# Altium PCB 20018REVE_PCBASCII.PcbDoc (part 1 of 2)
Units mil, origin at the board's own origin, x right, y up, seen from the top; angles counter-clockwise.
Board outline 3400 x 2150 mil, 4 copper layers (Top Layer, Signal Layer 1, Signal Layer 2, Bottom Layer), stack 66.258 mil thick; 182 components, 126 nets, 668 pads, 320 vias.
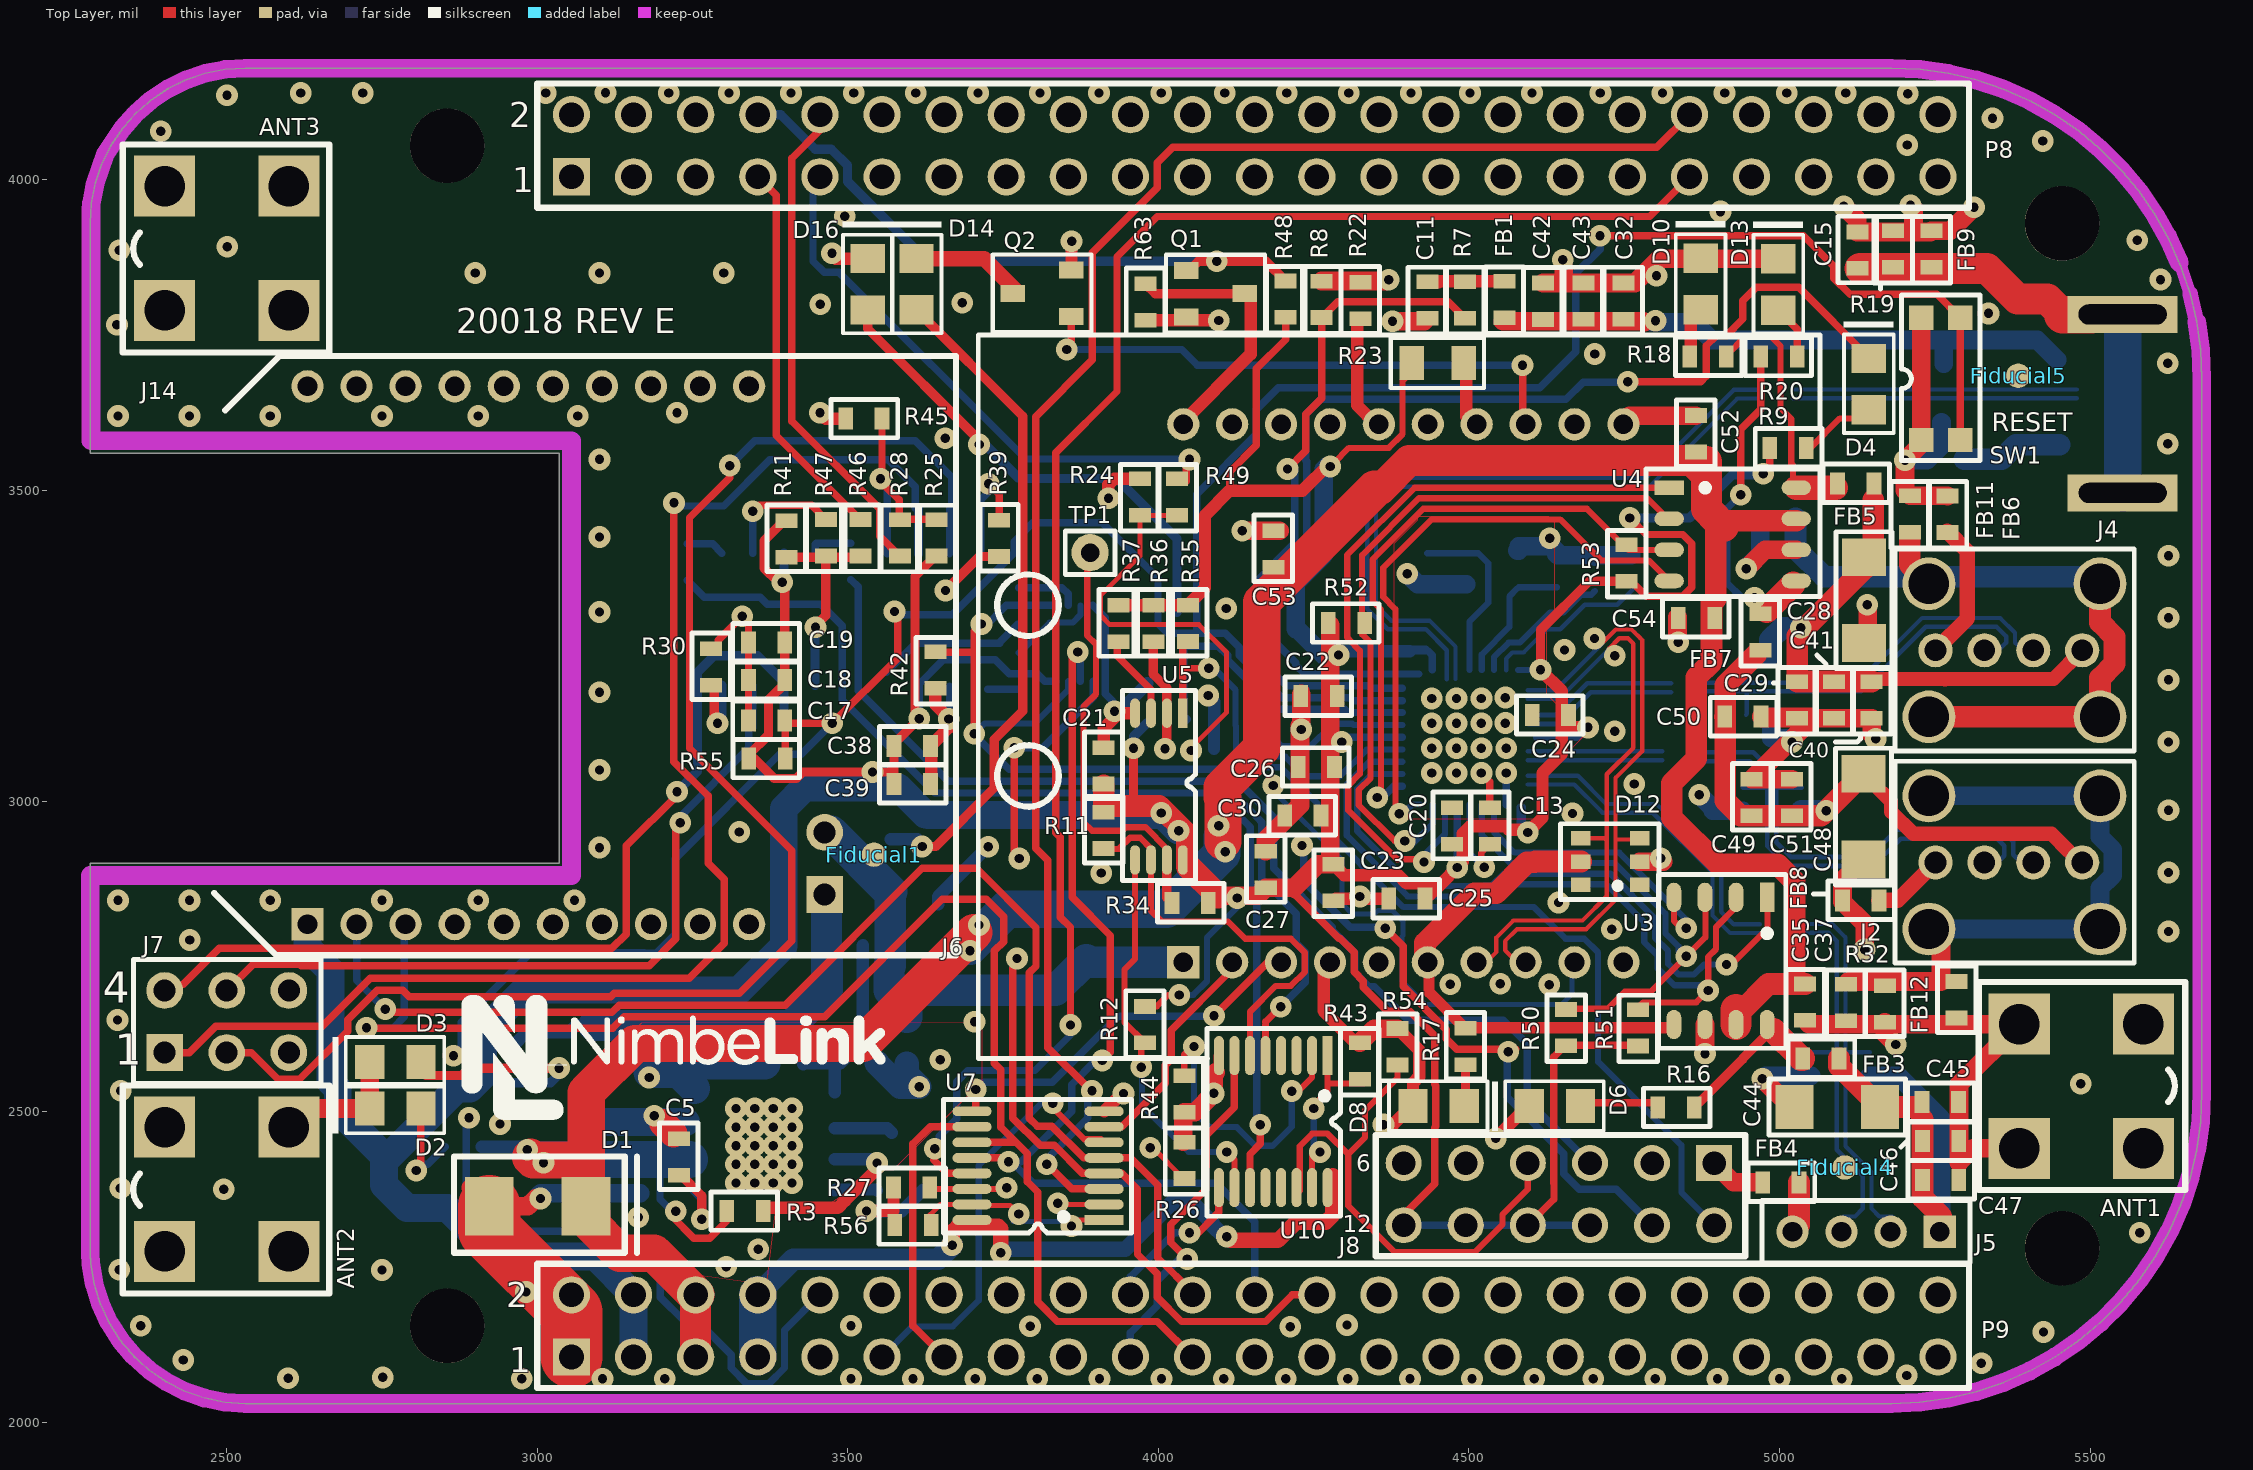
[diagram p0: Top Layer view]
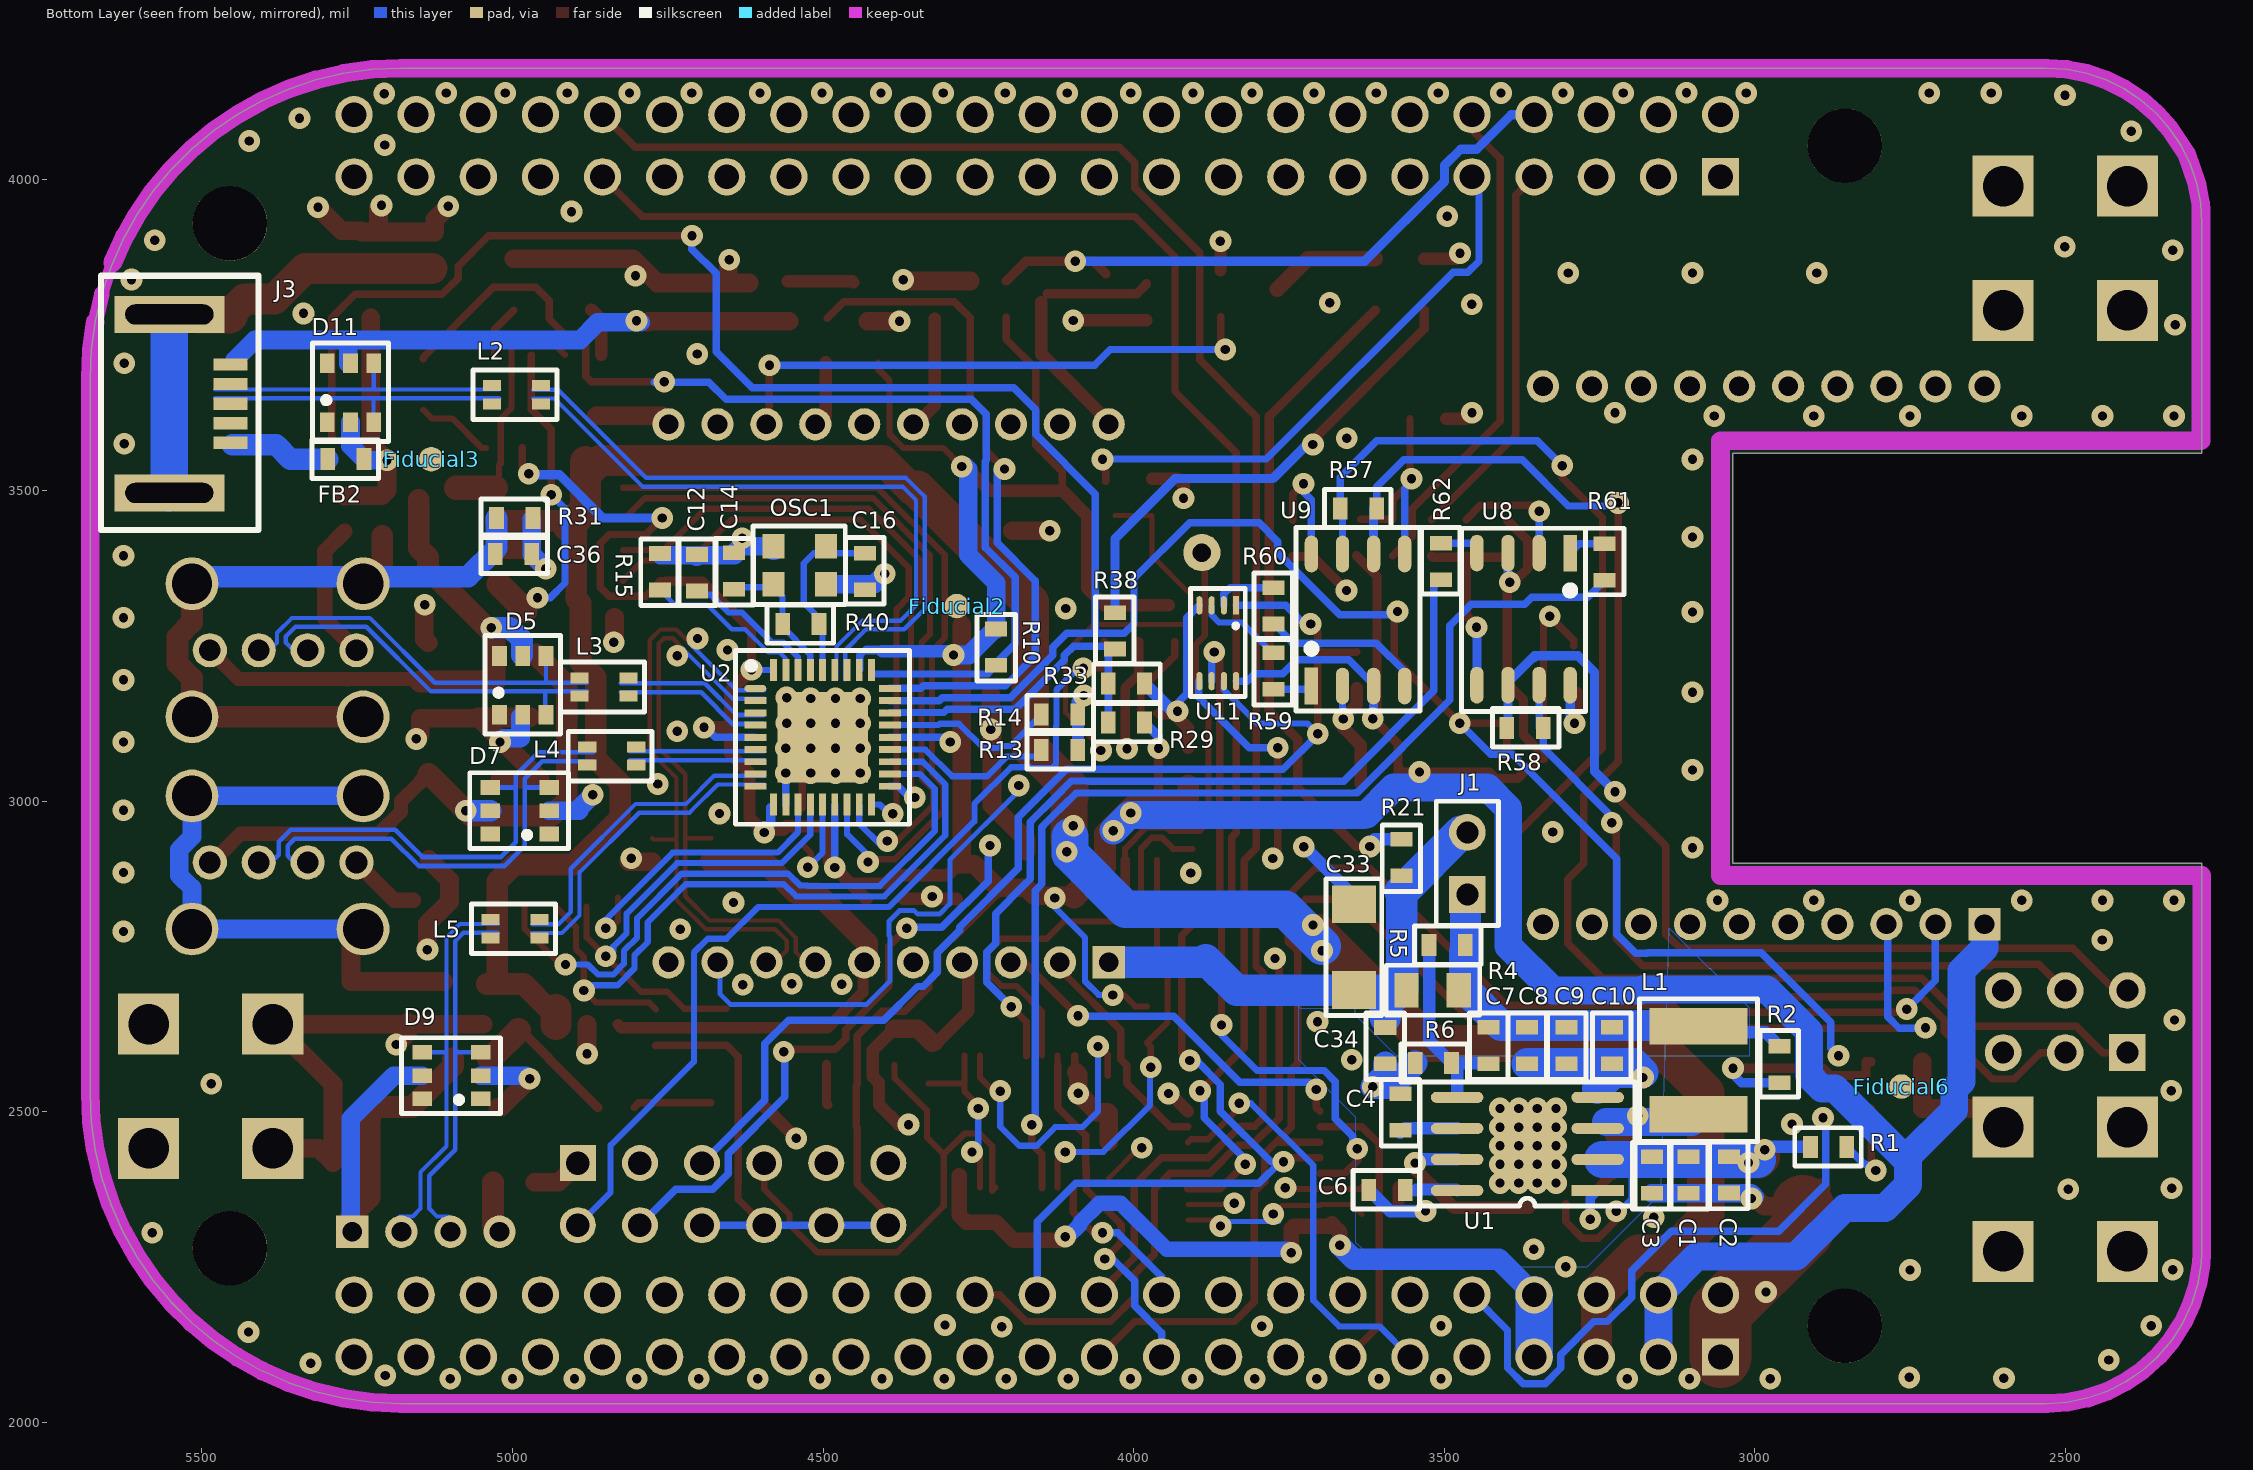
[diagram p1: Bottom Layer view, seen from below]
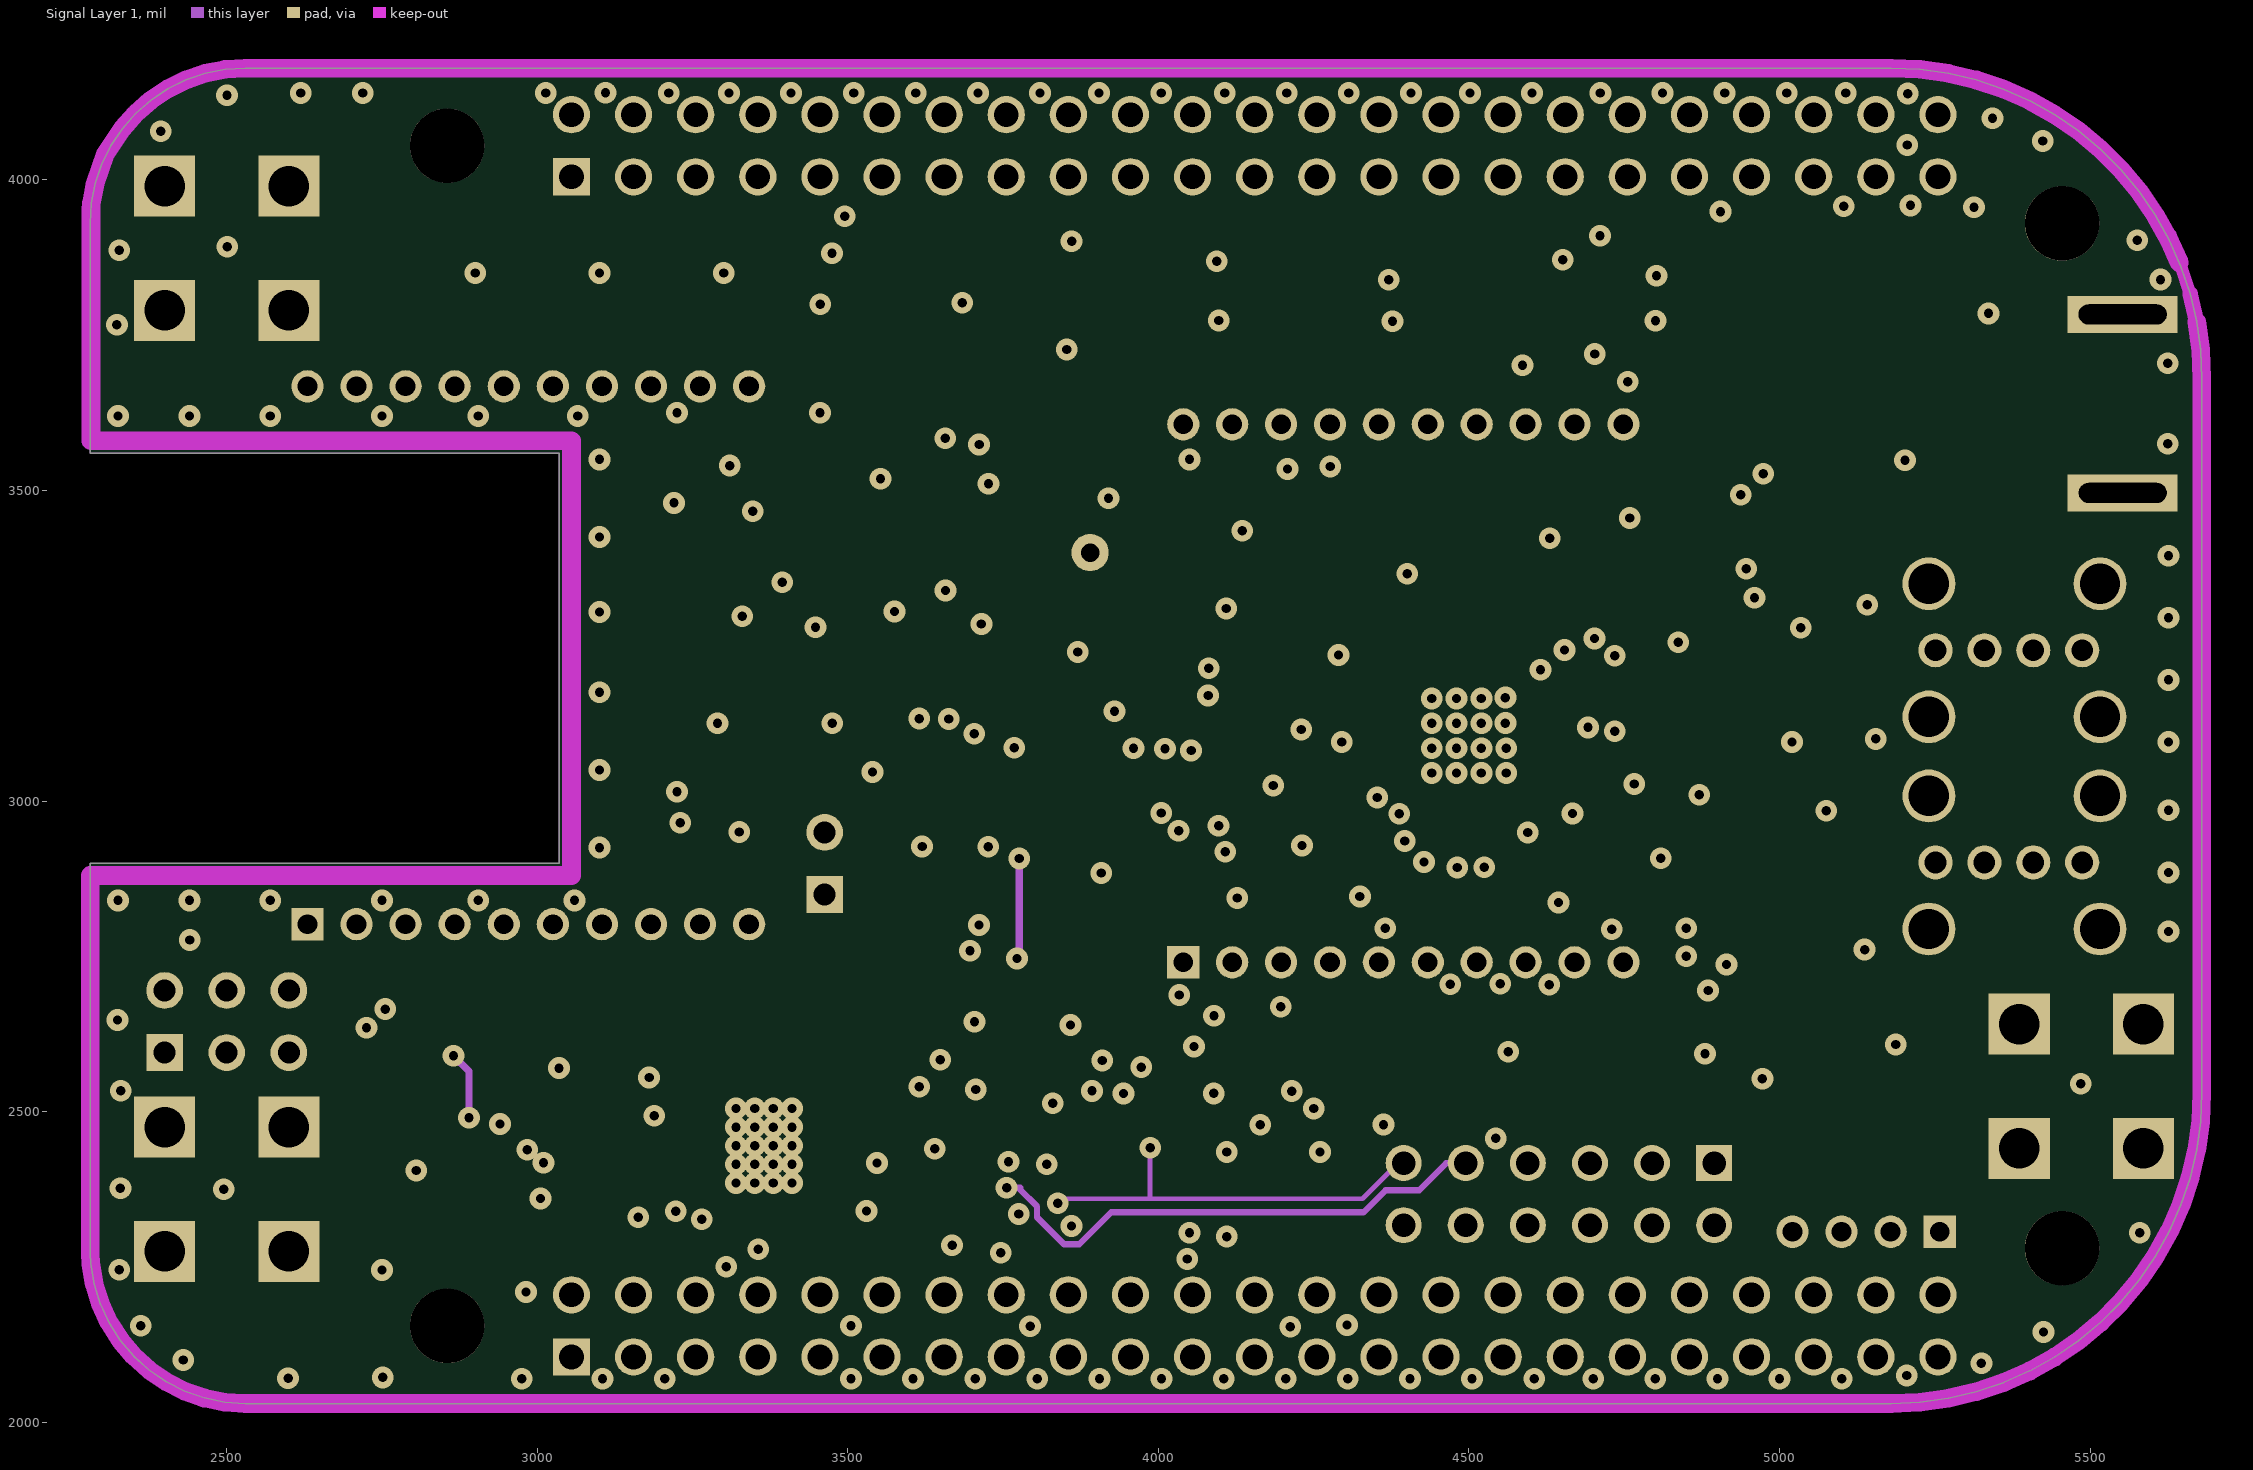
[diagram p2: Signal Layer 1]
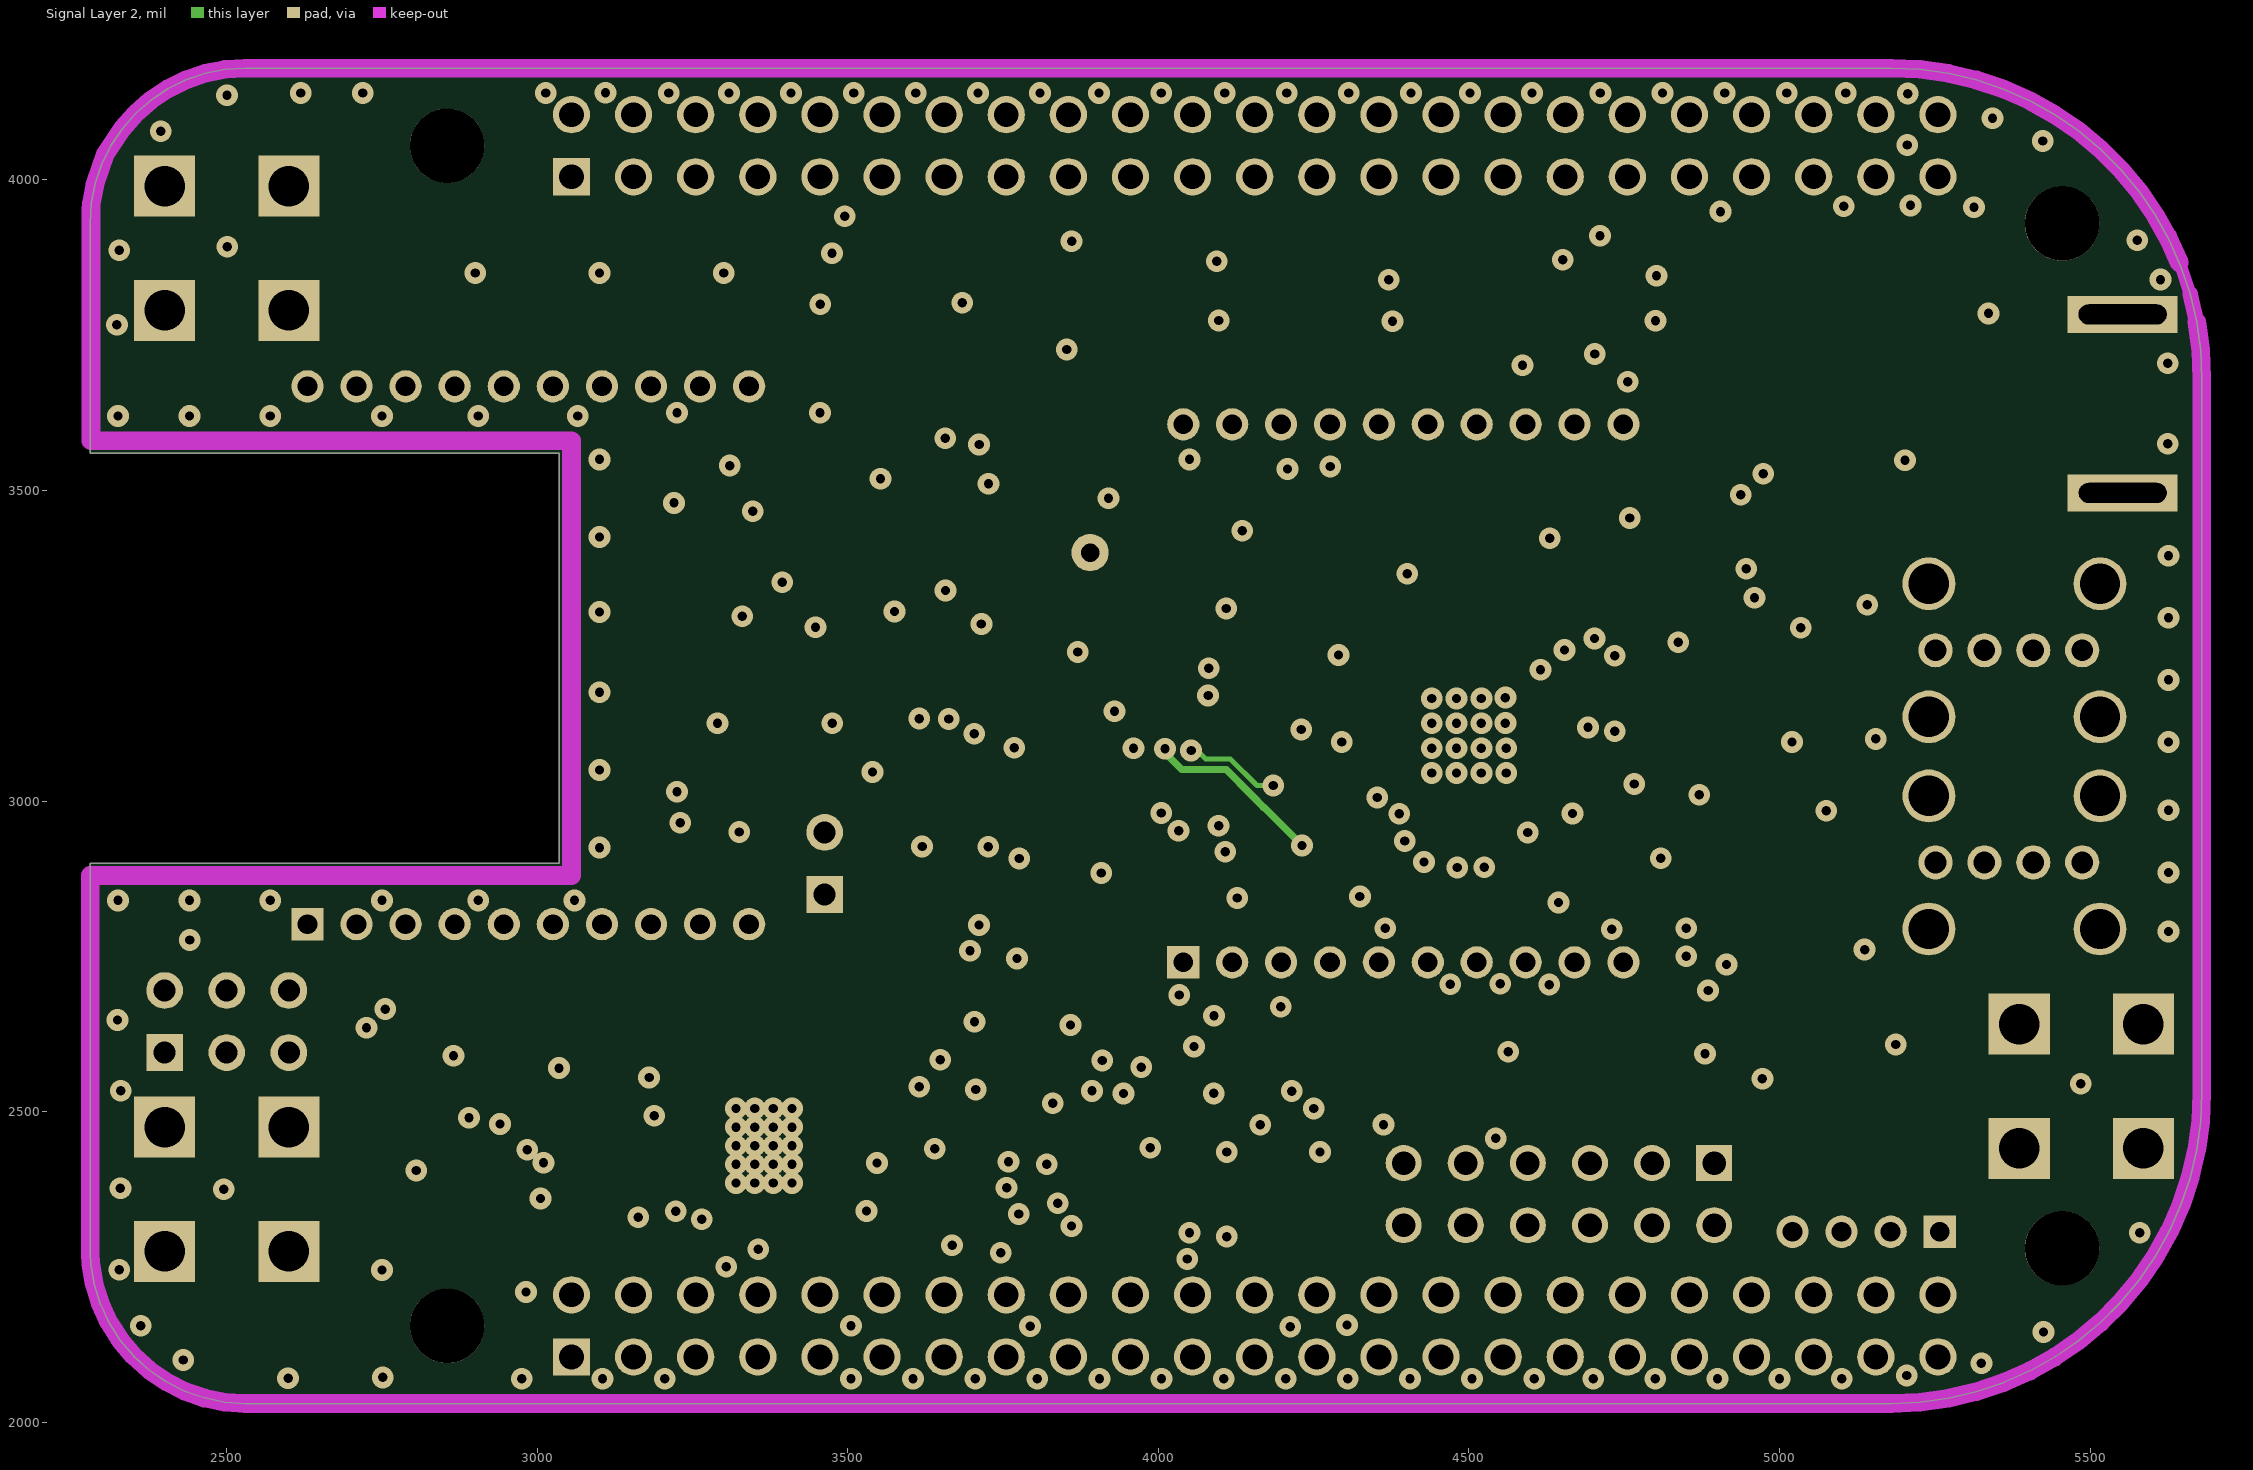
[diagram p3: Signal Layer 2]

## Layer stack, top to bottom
Top Solder: solder mask 0.4, Solder Resist, Dk 3.5
Top Layer: signal copper 1.4
Dielectric 1: prepreg 6.69, FR-4, Dk 4.6
Signal Layer 1: signal copper 1.417
Dielectric 3: core 47.244, Dk 4.6
Signal Layer 2: signal copper 1.417
Dielectric 2: prepreg 6.69, Dk 4.6
Bottom Layer: signal copper 1.4
Bottom Solder: solder mask 0.4, Solder Resist, Dk 3.5

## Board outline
2280,2600 2280,2900 3035,2900 3035,3560 2280,3560 2280,3570 2280,3930 2282.14,3962.63 2288.52,3994.7 2299.03,4025.67 2313.49,4055 2331.66,4082.19 2353.22,4106.78 2377.81,4128.34 2405,4146.51 2434.33,4160.97 2465.3,4171.48 2497.37,4177.86 2530,4180 5180,4180 5226.13,4177.87 5271.87,4171.49 5316.83,4160.91 5360.62,4146.24 5402.87,4127.58 5443.22,4105.11 5481.32,4079.01 5516.85,4049.5 5549.5,4016.85 5579.01,3981.32 5605.11,3943.22 5627.58,3902.87 5646.24,3860.62 5660.91,3816.83 5671.49,3771.87 5677.87,3726.13 5680,3680 5680,2530 5677.87,2483.87 5671.49,2438.12 5660.91,2393.17 5646.24,2349.38 5627.58,2307.13 5605.11,2266.78 5579.01,2228.68 5549.5,2193.15 5516.85,2160.5 5481.32,2130.99 5443.22,2104.89 5402.87,2082.42 5360.62,2063.76 5316.83,2049.09 5271.87,2038.51 5226.13,2032.13 5180,2030 2530,2030 2496.68,2032.23 2463.95,2038.88 2432.4,2049.84 2402.59,2064.9 2375.05,2083.81 2350.28,2106.21 2328.72,2131.72 2310.75,2159.87 2296.7,2190.17 2286.81,2222.07 2281.25,2255 2280.04,2272.11 2280,2320 2280,2483.93

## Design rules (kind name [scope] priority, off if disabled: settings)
AssemblyTestPointUsage [All] p0: scope1count=1 scope1_0_kind=Board scope1_0_value=Board scope2count=1 scope2_0_kind=Board scope2_0_value=Board commentlength=0
AssemblyTestpoint [All] p0: scope1count=1 scope1_0_kind=Board scope1_0_value=Board scope2count=1 scope2_0_kind=Board scope2_0_value=Board commentlength=0
Clearance Clearance_1 [All] p0 off: scope1count=1 scope1_0_kind=Board scope1_0_value=Board scope2count=1 scope2_0_kind=Board scope2_0_value=Board commentlength=69 gap=23.62 // Protel DXP Scope 1 Expression Was: (HasFootprint('Fiducial 1mm'))
Clearance [All] p0: scope1count=1 scope1_0_kind=Board scope1_0_value=Board scope2count=1 scope2_0_kind=Board scope2_0_value=Board commentlength=0 gap=7
Clearance Clearance_1 [(HasFootprint('Fiducial 1mm'))] p1: gap=23.62
Clearance [All] p2: gap=7
ComponentClearance ComponentClearance_1 [All] p0: scope1count=1 scope1_0_kind=Footprint scope1_0_value=BBBC scope2count=1 scope2_0_kind=Board scope2_0_value=Board commentlength=0 gap=0 collisioncheckmode=3
ComponentClearance [All] p0: scope1count=1 scope1_0_kind=Board scope1_0_value=Board scope2count=1 scope2_0_kind=Board scope2_0_value=Board commentlength=0 gap=7 collisioncheckmode=3
ComponentClearance ComponentClearance_1 [HasFootprint('BBBC')] p1: gap=0 collisioncheckmode=3 verticalgap=0 showdistances=FALSE
ComponentClearance [All] p2: gap=7 collisioncheckmode=3 verticalgap=7 showdistances=FALSE
DiffPairsRouting [All] p0: scope1count=1 scope1_0_kind=Board scope1_0_value=Board scope2count=1 scope2_0_kind=Board scope2_0_value=Board commentlength=0
DiffPairsRouting [All] p1: maxlimit=13 minlimit=7 mostfreqgap=7 toplayer_minwidth=7 toplayer_maxwidth=10 toplayer_prefwidth=7 midlayer1_minwidth=7 midlayer1_maxwidth=10 midlayer1_prefwidth=7 midlayer2_minwidth=7 midlayer2_maxwidth=10 midlayer2_prefwidth=7 bottomlayer_minwidth=7 bottomlayer_maxwidth=10 bottomlayer_prefwidth=7 maxuncoupledlength=500
FabricationTestPointUsage [All] p0: scope1count=1 scope1_0_kind=Board scope1_0_value=Board scope2count=1 scope2_0_kind=Board scope2_0_value=Board commentlength=0 valid=0 allowmultiple=FALSE
FabricationTestpoint [All] p0: scope1count=1 scope1_0_kind=Board scope1_0_value=Board scope2count=1 scope2_0_kind=Board scope2_0_value=Board commentlength=0 side=3 testpointundercomponent=TRUE minsize=40 maxsize=100 preferedsize=60 minholesize=0 maxholesize=40 preferedholesize=32 testpointgrid=1
FanoutControl Fanout_Default [All] p0: scope1count=1 scope1_0_kind=Board scope1_0_value=Board scope2count=1 scope2_0_kind=Board scope2_0_value=Board commentlength=30 // Fanout_Default (Default Rule)
FanoutControl Fanout_Small [All] p0 off: scope1count=1 scope1_0_kind=Board scope1_0_value=Board scope2count=1 scope2_0_kind=Board scope2_0_value=Board commentlength=84 // Protel DXP Scope 1 Expression Was: (CompPinCount < 5)   Fanout_Small (Default Rule)
FanoutControl Fanout_SOIC [All] p0 off: scope1count=1 scope1_0_kind=Board scope1_0_value=Board scope2count=1 scope2_0_kind=Board scope2_0_value=Board commentlength=71 // Protel DXP Scope 1 Expression Was: IsSOIC   Fanout_SOIC (Default Rule)
FanoutControl Fanout_LCC [All] p0 off: scope1count=1 scope1_0_kind=Board scope1_0_value=Board scope2count=1 scope2_0_kind=Board scope2_0_value=Board commentlength=69 // Protel DXP Scope 1 Expression Was: IsLCC   Fanout_LCC (Default Rule)
FanoutControl Fanout_BGA [All] p0 off: scope1count=1 scope1_0_kind=Board scope1_0_value=Board scope2count=1 scope2_0_kind=Board scope2_0_value=Board commentlength=69 // Protel DXP Scope 1 Expression Was: IsBGA   Fanout_BGA (Default Rule)
Height [All] p0: scope1count=1 scope1_0_kind=Board scope1_0_value=Board scope2count=1 scope2_0_kind=Board scope2_0_value=Board commentlength=0
Height [All] p1: minheight=0 maxheight=10000 prefheight=500
HoleSize [All] p0: scope1count=1 scope1_0_kind=Board scope1_0_value=Board scope2count=1 scope2_0_kind=Board scope2_0_value=Board commentlength=0 absolutevalues=TRUE maxlimit=500 minlimit=15 maxpercent=80.000 minpercent=20.000
HoleSize [All] p1: absolutevalues=TRUE maxlimit=500 minlimit=15 maxpercent=80.000 minpercent=20.000
HoleToHoleClearance [All] p0: scope1count=1 scope1_0_kind=Board scope1_0_value=Board scope2count=1 scope2_0_kind=Board scope2_0_value=Board commentlength=0
HoleToHoleClearance [All] p1: gap=7 allowstackedmicrovias=TRUE
LayerPairs [All] p0: scope1count=1 scope1_0_kind=Board scope1_0_value=Board scope2count=1 scope2_0_kind=Board scope2_0_value=Board commentlength=0 enforce=TRUE
MatchedLengths [All] p0: scope1count=1 scope1_0_kind=NetClass scope1_0_value=DIFF90 scope2count=1 scope2_0_kind=Board scope2_0_value=Board commentlength=0 tolerance=1000 amplitude=200 gap=20 style=90-Degree
MatchedLengths [InNetClass('DIFF90')] p1: tolerance=1000 checknetsindiffpair=TRUE checkdiffpairvsdiffpair=TRUE checkothers=TRUE
MinimumAnnularRing [All] p0: scope1count=1 scope1_0_kind=Board scope1_0_value=Board scope2count=1 scope2_0_kind=Board scope2_0_value=Board commentlength=0 minimumring=10
MinimumAnnularRing [All] p1: minimumring=10
MinimumSolderMaskSliver [All] p0: scope1count=1 scope1_0_kind=Board scope1_0_value=Board scope2count=1 scope2_0_kind=Board scope2_0_value=Board commentlength=0
MinimumSolderMaskSliver [All] p1: minsoldermaskwidth=0
NetAntennae [All] p0: scope1count=1 scope1_0_kind=Board scope1_0_value=Board scope2count=1 scope2_0_kind=Board scope2_0_value=Board commentlength=0
PasteMaskExpansion [All] p0: scope1count=1 scope1_0_kind=Board scope1_0_value=Board scope2count=1 scope2_0_kind=Board scope2_0_value=Board commentlength=0 expansion=0
PlaneClearance [All] p0: scope1count=1 scope1_0_kind=Board scope1_0_value=Board scope2count=1 scope2_0_kind=Board scope2_0_value=Board commentlength=0 clearance=30
PlaneClearance [All] p1: clearance=30
PlaneConnect [All] p0: scope1count=1 scope1_0_kind=Board scope1_0_value=Board scope2count=1 scope2_0_kind=Board scope2_0_value=Board commentlength=0 planeconnectstyle=Direct reliefexpansion=20 reliefentries=4 reliefconductorwidth=20 reliefairgap=10
PlaneConnect [All] p1: planeconnectstyle=Direct reliefexpansion=20 reliefentries=4 reliefconductorwidth=20 reliefairgap=10
PolygonConnect [All] p0: scope1count=1 scope1_0_kind=Board scope1_0_value=Board scope2count=1 scope2_0_kind=Board scope2_0_value=Board commentlength=0 connectstyle=Direct reliefconductorwidth=10 reliefentries=4 polygonreliefangle="90 Angle"
PolygonConnect [All] p1: connectstyle=Direct reliefconductorwidth=10 reliefentries=4 polygonreliefangle="90 Angle" airgapwidth=10
RoutingCorners [All] p0: scope1count=1 scope1_0_kind=Board scope1_0_value=Board scope2count=1 scope2_0_kind=Board scope2_0_value=Board commentlength=0 cornerstyle=45-Degree minsetback=100 maxsetback=100
RoutingLayers [All] p0: scope1count=1 scope1_0_kind=Board scope1_0_value=Board scope2count=1 scope2_0_kind=Board scope2_0_value=Board commentlength=0 top layer=Automatic mid layer 1=Automatic mid layer 2=Automatic bottom layer=Automatic
RoutingPriority [All] p0: scope1count=1 scope1_0_kind=NetClass scope1_0_value=DIFF90 scope2count=1 scope2_0_kind=Board scope2_0_value=Board commentlength=0
RoutingPriority [InNetClass('DIFF90')] p1: routingpriority=0
RoutingTopology [All] p0: scope1count=1 scope1_0_kind=Board scope1_0_value=Board scope2count=1 scope2_0_kind=Board scope2_0_value=Board commentlength=0 topology=Shortest
RoutingVias [All] p0: scope1count=1 scope1_0_kind=Board scope1_0_value=Board scope2count=1 scope2_0_kind=Board scope2_0_value=Board commentlength=0 holewidth=15 width=35 viastyle="Through Hole" minholewidth=15 minwidth=35 maxholewidth=250 maxwidth=350
RoutingVias [All] p1: holewidth=15 width=35 viastyle="Through Hole" minholewidth=15 minwidth=35 maxholewidth=250 maxwidth=350
ShortCircuit [All] p0: scope1count=1 scope1_0_kind=Board scope1_0_value=Board scope2count=1 scope2_0_kind=Board scope2_0_value=Board commentlength=0 allowed=FALSE
SilkToBoardRegionClearance [All] p0: scope1count=1 scope1_0_kind=Board scope1_0_value=Board scope2count=1 scope2_0_kind=Board scope2_0_value=Board commentlength=0
SilkToSilkClearance [All] p0: scope1count=1 scope1_0_kind=Board scope1_0_value=Board scope2count=1 scope2_0_kind=Board scope2_0_value=Board commentlength=0
SilkToSilkClearance [All] p1: silktosilkclearance=0
SilkToSolderMaskClearance [All] p0 off: scope1count=1 scope1_0_kind=Board scope1_0_value=Board scope2count=1 scope2_0_kind=Board scope2_0_value=Board commentlength=44 // Protel DXP Scope 1 Expression Was: IsPad
SilkToSolderMaskClearance [IsPad] p1: minsilkscreentomaskgap=0 clearancetoexposedcopper=TRUE
SolderMaskExpansion [All] p0: scope1count=1 scope1_0_kind=Board scope1_0_value=Board scope2count=1 scope2_0_kind=Board scope2_0_value=Board commentlength=0 expansion=0
SolderMaskExpansion [All] p1: expansion=0
UnRoutedNet [All] p0: scope1count=1 scope1_0_kind=Board scope1_0_value=Board scope2count=1 scope2_0_kind=Board scope2_0_value=Board commentlength=0
UnpouredPolygon [All] p0: scope1count=1 scope1_0_kind=Board scope1_0_value=Board scope2count=1 scope2_0_kind=Board scope2_0_value=Board commentlength=0
UnpouredPolygon [All] p1: allowunpoured=FALSE
Width [All] p0: scope1count=1 scope1_0_kind=Board scope1_0_value=Board scope2count=1 scope2_0_kind=Board scope2_0_value=Board commentlength=0 maxlimit=250 minlimit=7 preferedwidth=12
Width [All] p1: maxlimit=250 minlimit=7 preferedwidth=12
18 further rules are at their usual default settings.

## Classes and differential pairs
component class "Beagle Bone Black C Cape CAN": C18 C19 C38 C39 J7 R25 R28 R30 R39 R41 R42 R43 R44 R45 R46 R47 R54 R57 R58 R59 R60 R61 R62 U8 U9 U10 U11
net class DIFF90: SKY_USBD-_N SKY_USBD-_P USB_F_P2_N USB_F_P2_P USB_F_P4_N USB_F_P4_P USB_P2_N USB_P2_P USB_P3_N USB_P3_P USB_P4_N USB_P4_P USB_UP_N USB_UP_P USBL_F_P3_N USBL_F_P3_P USBL_F_UP_N USBL_F_UP_P
component class "Beagle Bone Black C Cape USB": C11 C12 C13 C14 C15 C16 C20 C22 C23 C24 C25 C26 C27 C28 C29 C30 C32 C35 C36 C37 C40 C41 C42 C43 C44 C45 C46 C47 C48 C49 C50 C51 C52 C53 C54 D4 D5 D6 D7 D8 D9 D10 D11 D12 D13 D16 FB1 FB2 FB3 FB4 FB5 FB6 FB7 FB8 FB9 FB11 FB12 J2 J3 J4 J5 L2 L3 L4 L5 OSC1 R7 R8 R9 R10 R13 R14 R15 R16 R17 R18 R19 R20 R29 R31 R32 R33 R38 R40 R50 R51 R52 R53 U2 U3 U4
component class "Beagle Bone Black C Cape XBEE and BBBC Header": C17 C21 Fiducial1 Fiducial2 Fiducial3 Fiducial4 Fiducial5 Fiducial6 J8 J14 P8 P9 R11 R12 R26 R27 R34 R35 R36 R37 R49 R55 R56 SW1 TP1 U5 U7
component class Power_2A_5Vto4VTI: C1 C2 C3 C4 C5 C6 C7 C8 C9 C10 D1 D2 D3 J1 L1 R1 R2 R3 R4 R5 R6 U1
component class "Skywire BBBC": ANT1 ANT2 ANT3 C33 C34 D14 J6 Q1 Q2 R21 R22 R23 R24 R48 R63
differential pair USB_F_P4: +USB_F_P4_P -USB_F_P4_N
differential pair SKY_USBD-: +SKY_USBD-_P -SKY_USBD-_N
differential pair USB_P4: +USB_P4_P -USB_P4_N
differential pair USB_P2: +USB_P2_P -USB_P2_N
differential pair USB_P3: +USB_P3_P -USB_P3_N
differential pair USB_UP: +USB_UP_P -USB_UP_N
differential pair USB_F_P2: +USB_F_P2_P -USB_F_P2_N
differential pair USBL_F_P3: +USBL_F_P3_P -USBL_F_P3_N
differential pair " ": +USBL_F_UP_P -USBL_F_UP_N

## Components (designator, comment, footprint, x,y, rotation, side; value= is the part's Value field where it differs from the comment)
ANT1 "UFL to SMA Antenna Mount" "UFL TO SMA" 5585.83,2440.73 r90 top locked
ANT2 "UFL to SMA Antenna Mount" "UFL TO SMA" 2400,2475 r270 top locked
ANT3 "UFL to SMA Antenna Mount" "UFL TO SMA" 2400,3990 r270 top
C1 "10uF" 0603 3106.35,2403.41 r270 bottom
C2 "10uF" 0603 3041.54,2403.86 r270 bottom
C3 "0.1uF" 0603 3165.72,2403.41 r270 bottom
C4 "0.47uF" 0603 3570.51,2504.93 r270 bottom
C5 "0.1uF" 0603 3227.87,2421.35 r90 top
C6 "0.1uF" 0603 3586.19,2374.06 r0 bottom
C7 "22pF" 0603 3428.31,2612 r270 bottom
C8 "10uF" 0603 3366.23,2611.99 r270 bottom
C9 "10uF" 0603 3302.79,2612 r270 bottom
C10 "10uF" 0603 3230.04,2612.03 r270 bottom
C11 "1uF" 0603 4432.92,3812.49 r270 top
C12 "0.1uF" 0603 4702.89,3361.85 r90 bottom
C13 "0.1uF" 0603 4533.76,2954.2 r90 top
C14 "18pF" 0603 4643.09,3376.05 r270 bottom
C15 "NP" 0603 5125.26,3881.18 r90 top
C16 "18pF" 0603 4432.71,3364 r90 bottom
C17 "NP 1uF" 0603 3375,3130 r180 top
C18 "0.1uF" 0603 3375,3195 r180 top
C19 "10uF" 0603 3375,3255 r180 top
C20 "0.1uF" 0603 4472.87,2953.97 r90 top
C21 "0.1uF" 0603 3911.8,3050.93 r90 top
C22 "0.1uF" 0603 4264.34,3168.99 r180 top
C23 "0.1uF" 0603 4281.49,2874.48 r270 top
C24 "0.1uF" 0603 4636.72,3138.74 r180 top
C25 "0.1uF" 0603 4405.64,2842.7 r180 top
C26 "0.1uF" 0603 4260,3055 r180 top
C27 "1uF" 0603 4172.8,2883.88 r90 top
C28 "100uF 6.3V" 1206 5135.93,3323.51 r270 top
C29 "0.1uF" 0603 5028.42,3168.35 r270 top
C30 "4.7uF" 0603 4238.21,2976.47 r180 top
C32 "0.1uF" 0603 4748.67,3799.09 r90 top
C33 "100uF 6.3V" 1206 3645.39,2764.91 r90 bottom
C34 "0.1uF" 0603 3594.8,2611.83 r270 bottom
C35 "4.7uF" 0603 5041.37,2681.79 r270 top
C36 "NP" 0603 5003.92,3397.33 r180 bottom
C37 "NP" 0603 5106.61,2681.21 r270 top
C38 "0.1uF" 0603 3597.96,3088.71 r0 top
C39 "10uF" 0603 3597.96,3027.6 r0 top
C40 "1uF" 0603 5148.3,3168.41 r270 top
C41 "1nF" 0603 5087.83,3168.35 r270 top
C42 "1uF" 0603 4619.13,3798.95 r90 top
C43 "1nF" 0603 4684.01,3799.09 r90 top
C44 "100uF 6.3V" 1206 5092.88,2507.24 r180 top
C45 "1uF" 0603 5253.12,2515.25 r0 top
C46 "1nF" 0603 5253.69,2452.29 r0 top
C47 "0.1uF" 0603 5253.69,2389.91 r0 top
C48 "100uF 6.3V" 1206 5135,2975 r270 top
C49 "1nF" 0603 4955,3000 r90 top
C50 "1uF" 0603 4935.27,3135.77 r0 top
C51 "0.1uF" 0603 5020,3000 r90 top
C52 "4.7uF" 0603 4865.25,3585.57 r90 top
C53 "0.1uF" 0603 4185,3400 r90 top
C54 "0.1uF" 0603 4872,3295.05 r180 top
D1 "D_TVS DIODE 13.6VWM 22.5VC SMBJ" D_SMBJP6KE16A-TP 3000.66,2347.65 r0 top
D2 "D_LED_GREEN" D_LED_GREEN 2730,2505 r0 top
D3 "D_LED_GREEN" D_LED_GREEN 2730,2580 r0 top
D4 "D_LED_GREEN" D_LED_GREEN 5143.71,3712.4 r270 top
D5 "D5V0F4U6SO-7" D5V0F4U6SO-7 4983.44,3186.24 r90 bottom
D6 "NP" D_LED_GREEN 4596.95,2508.9 r0 top
D7 "D5V0F4U6SO-7" D5V0F4U6SO-7 4988.3,2984.43 r0 bottom
D8 "NP" D_LED_GREEN 4409.86,2508.9 r0 top
D9 "D5V0F4U6SO-7" D5V0F4U6SO-7 5098.03,2557.89 r0 bottom
D10 "NP" D_LED_GREEN 4873.04,3873.8 r270 top
D11 "D5V0F4U6SO-7" D5V0F4U6SO-7 5260.83,3657.28 r90 bottom
D12 "D5V0F4U6SO-7" D5V0F4U6SO-7 4727.47,2902.46 r180 top
D13 "NP" D_LED_GREEN 4997.94,3872.93 r270 top
D14 "D_LED_GREEN" D_LED_GREEN 3610.69,3873.35 r270 top
D16 "D_LED_GREEN" D_LED_GREEN 3532.15,3873.33 r270 top
FB1 "FB 7.5A 22Ohm 0.04DCR 0603" 0603 4557.2,3813.1 r270 top
FB2 "FB 7.5A 22Ohm 0.04DCR 0603" 0603 5262.61,3550.32 r0 bottom
FB3 "FB 7.5A 22Ohm 0.04DCR 0603" 0603 5060.83,2585.64 r0 top
FB4 "FB 7.5A 22Ohm 0.04DCR 0603" 0603 4996.36,2385.95 r0 top
FB5 "FB 7.5A 22Ohm 0.04DCR 0603" 0603 5116.95,3511.42 r0 top
FB6 "FB 7.5A 22Ohm 0.04DCR 0603" 0603 5270.42,3467.4 r270 top
FB7 "FB 7.5A 22Ohm 0.04DCR 0603" 0603 4969.02,3277.76 r270 top
FB8 "FB 7.5A 22Ohm 0.04DCR 0603" 0603 5125,2840 r0 top
FB9 "FB 7.5A 22Ohm 0.04DCR 0603" 0603 5244.5,3894.52 r270 top
FB11 "FB 7.5A 22Ohm 0.04DCR 0603" 0603 5210.38,3467.83 r270 top
FB12 "FB 7.5A 22Ohm 0.04DCR 0603" 0603 5285.17,2674.35 r90 top
Fiducial1 "Fiducial 1mm" "Fiducial 1mm"#1 3542.03,2913.72 r90 top
Fiducial2 "Fiducial 1mm" "Fiducial 1mm"#1 4284.73,3313.9 r90 bottom
Fiducial3 "Fiducial 1mm" "Fiducial 1mm"#2 5130.41,3550.25 r90 bottom
Fiducial4 "Fiducial 1mm" "Fiducial 1mm"#1 5105,2410 r90 top
Fiducial5 "Fiducial 1mm" "Fiducial 1mm"#1 5384.09,3684.71 r90 top
Fiducial6 "Fiducial 1mm" "Fiducial 1mm"#1 2763.72,2540.33 r90 bottom
J1 "NP" HDR1X2 3462.69,2849.58 r90 bottom
J2 "USB A REC" "USBA FCI VERT" 5516,2794.04 r90 top locked
J3 "USB MINI B" "USB MINI B" 5454.07,3639.73 r270 bottom locked
J4 "USB A REC" "USBA FCI VERT" 5516,3135.62 r90 top locked
J5 "NP" "HEADER 4PIN 2MMPITCH" 5256.82,2306.54 r270 top
J6 "Skywire socket" "SKYWIRE SOCKET" 4040,2740.37 r90 top locked
J7 "Header 3X2A" HDR2X3_CEN 2400,2595 r0 top
J8 "HEADER 6x2 .1\" Pitch" "HEADER 6x2 .1\" Pitch" 4894.78,2417.09 r270 top
J14 "J Xbee Pro" "XBEEPRO RPSMA" 2630,2801.69 r90 top locked
L1 "6.8uH" NR5030 3090.45,2566.57 r90 bottom
L2 "SRF2012-900YA" SRF2012-900YA 4993.48,3654.09 r180 bottom
L3 "SRF2012-900YA" SRF2012-900YA 4852.66,3183.46 r180 bottom
L4 "SRF2012-900YA" SRF2012-900YA 4840.19,3072.17 r180 bottom
L5 "SRF2012-900YA" SRF2012-900YA 4995.9,2794.41 r180 bottom
OSC1 "24MHz" "OSC 008-0288-0_F" 4580,3410 r180 bottom
P8 "BBBC Socket P8" BBBC 3055,4005 r90 top locked
P9 "BBBC Socket P9" BBBC 3055,2105 r90 top locked
Q1 "N-Ch" SOT-23-3 4044.55,3854.3 r270 top
Q2 "N-Ch" SOT-23-3 3860,3780 r90 top
R1 "1K" 0603 2875.29,2443.14 r0 bottom
R2 "124" 0603 2960,2570 r90 bottom
R3 "10K" 0603 3340,2340 r180 top
R4 "0.1" 0805 3509.39,2695.3 r180 bottom
R5 "93.1K 1%" 0603 3500.79,2767.85 r180 bottom
R6 "22.1K 1%" 0603 3523.09,2577.98 r180 bottom
R7 "100K" 0603 4493.22,3812.49 r270 top
R8 "100K" 0603 4262.82,3813.44 r270 top
R9 "1K" 0603 5007.79,3568.55 r0 top
R10 "100K" 0603 4221.26,3253.38 r270 bottom
R11 "5.6k 1%" 0603 3911.96,2947.08 r90 top
R12 "5.6k 1%" 0603 3978.41,2634.28 r90 top
R13 "100K" 0603 4124.99,3082.52 r180 bottom
R14 "100K" 0603 4124.96,3139.21 r180 bottom
R15 "12K" 0603 4762.7,3374.76 r270 bottom
R16 "NP 330" 0603 4827.76,2506.59 r0 top
R17 "NP 330" 0603 4494.4,2599.24 r90 top
R18 "NP 330" 0603 4879.29,3715.73 r0 top
R19 "NP" 0603 5182.72,3894.54 r270 top
R20 "NP 330" 0603 5004.86,3715.73 r180 top
R21 "124" 0603 3568.84,2914.8 r270 bottom
R22 "10K" 0603 4325,3800 r90 top
R23 "0.1" 0805 4440.59,3705.12 r180 top
R24 "10K" 0603 3970,3495 r270 top
R25 "10K" 0603 3642.89,3429.39 r270 top
R26 "10K" 0603 4041.78,2427.19 r270 top
R27 "10K" 0603 3597.09,2378.03 r0 top
R28 "NP" 0603 3584.26,3429.39 r270 top
R29 "NP" 0603 4017.28,3126.27 r180 bottom
R30 "10K" 0603 3280,3210 r90 top
R31 "NP" 0603 4990.67,3455.42 r0 bottom
R32 "NP" 0603 5169.56,2667.48 r90 top
R33 "100K" 0603 4017.28,3189.51 r180 bottom
R34 "10K" 0603 4045.48,2835.92 r0 top
R35 "4.75k 1%" 0603 4047.28,3280.43 r90 top (schematic designator R36)
R36 "4.75k 1%" 0603 3991.69,3280.13 r90 top (schematic designator R35)
R37 "4.75k 1%" 0603 3935.65,3279.97 r90 top
R38 "330" 0603 4030,3268.37 r90 bottom
R39 "10K" 0603 3743.53,3417.2 r90 top
R40 "NP 1M" 0603 4530,3285 r0 bottom
R41 "10K" 0603 3401.1,3416.27 r90 top
R42 "10K" 0603 3640.73,3216.51 r270 top
R43 "10K" 0603 4324.26,2587.01 r270 top
R44 "10K" 0603 4041.73,2533.93 r270 top
R45 "NP" 0603 3519.99,3615.71 r0 top
R46 "NP" 0603 3520.37,3429.54 r270 top
R47 "NP" 0603 3464.59,3429.53 r270 top
R48 "1K" 0603 4204.83,3813.64 r270 top
R49 "0" 0603 4030,3495 r270 top
R50 "10K" 0603 4772.4,2640.51 r270 top
R51 "10K" 0603 4656.26,2640.84 r270 top
R52 "10K" 0603 4308.32,3286.74 r180 top
R53 "10K" 0603 4753.9,3388.95 r270 top
R54 "10K" 0603 4385,2610 r270 top
R55 "NP 10K" 0603 3375.55,3068.43 r180 top
R56 "10K" 0603 3610.63,2317.39 r180 top
R57 "120" 0603 3632.21,3470.93 r0 bottom
R58 "120" 0603 3375.45,3117.82 r180 bottom
R59 "33" 0603 3775,3215 r270 bottom
R60 "33" 0603 3775,3320 r270 bottom
R61 "33" 0603 3241.52,3378.96 r90 bottom
R62 "33" 0603 3505,3380 r90 bottom
R63 "NP" 0603 3979.33,3797.58 r90 top
SW1 "SW KMR231GLFS" KMR231GLFS 5227.98,3581.26 r90 top
TP1 "Test Point" TP 3890,3400 r0 top
U1 "U_TPS54229DDA" TPS54229DDA 3252.84,2372.92 r0 bottom locked
U2 "U USB2514B" USB2514 4500.72,3102.52 r180 bottom locked
U3 "U MIC2026" MIC2026 4979.95,2836.99 r270 top
U4 "U MIC2026" MIC2026 4830.13,3504.31 r0 top
U5 "CAT24C256" "TSSOP8 4.4x3 CASE 948AL-01" 4039.25,3141.34 r270 top
U7 "U MUX 2-1:4" SN74CBT3253CDBQR 3912.48,2325.47 r180 top
U8 "SN65HVD234DR" SOIC8 3297.19,3399.15 r270 bottom
U9 "SN65HVD234DR" SOIC8 3713.66,3185.12 r90 bottom
U10 "U MUX 2-1:4" SN74CBT3253CDBQR 4272.42,2590.14 r270 top
U11 "U SN74LVC2G125" SN74LVC2G125DCUR 3835,3315 r270 bottom

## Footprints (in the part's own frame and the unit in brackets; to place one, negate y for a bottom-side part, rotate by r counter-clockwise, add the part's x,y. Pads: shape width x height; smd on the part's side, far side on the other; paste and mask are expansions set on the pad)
0603 [mm]
  rect 0.6x0.9 smd: 1(-0.6,0) 2(0.889,0)
  silkscreen extent -1.19,-0.78 1.53,0.79
0805 [mm]
  rect 1x1.4 smd: 1(-1.3,0) 2(0.838,0)
  silkscreen extent -2.12,-1.03 1.69,1.02
1206 [mm]
  rect 1.55x1.8 smd: 1(-1.75,0) 2(1.75,0)
  silkscreen extent -2.79,-1.14 2.79,1.14
BBBC [mil]
  rect 60x60 hole 40: 1(0,0)
  round 60 hole 40: 2(100,0) 3(0,-100) 4(100,-100) 5(0,-200) 6(100,-200) 7(0,-300) 8(100,-300) 9(0,-400) 10(100,-400) 11(0,-500) 12(100,-500) 13(0,-600) 14(100,-600) 15(0,-700) 16(100,-700) 17(0,-800) 18(100,-800) 19(0,-900) 20(100,-900) 21(0,-1000) 22(100,-1000) 23(0,-1100) 24(100,-1100) 25(0,-1200) 26(100,-1200) 27(0,-1300) 28(100,-1300) 29(0,-1400) 30(100,-1400) 31(0,-1500) 32(100,-1500) 33(0,-1600) 34(100,-1600) 35(0,-1700) 36(100,-1700) 37(0,-1800) 38(100,-1800) 39(0,-1900) 40(100,-1900) 41(0,-2000) 42(100,-2000) 43(0,-2100) 44(100,-2100) 45(0,-2200) 46(100,-2200)
  silkscreen extent -50,-2250 150,55
D5V0F4U6SO-7 [mm] "SOT23, 6-Leads, Body 3.00x2.85mm, Pitch 0.95mm, IPC Medium Density"
  rect 0.8x0.6 smd: 1(-1.2,0.95) 2(-1.2,0) 3(-1.2,-0.95) 4(1.2,-0.95) 5(1.2,0) 6(1.2,0.95)
  silkscreen extent -1.99,-1.55 2.04,1.55
D_LED_GREEN [mm]
  rect 1.2x1.4 smd: 1(2.1,0) 2(0,0)
  silkscreen extent -1.52,-1.03 3.05,1.02
D_SMBJP6KE16A-TP [mm]
  rect 2x2.4 smd: A(-1.981,0) K(1.981,0)
  silkscreen extent -3.43,-1.91 4.06,2.03
"Fiducial 1mm"#1 [mm]
  round 1 smd paste+0.5 mask+0.5: Fiducial(0,0)
"Fiducial 1mm"#2 [mm]
  round 1 smd paste+0.5 mask+0.5: Fiducial(0,0.008)
HDR1X2 [mm] "Connector; Header; 2 Position"
  rect 1.5x1.5 hole 0.9: 1(0,0)
  round 1.5 hole 0.9: 2(2.54,0)
  silkscreen extent -1.27,-1.27 3.81,1.27
HDR2X3_CEN [mm] "Connector; Header; 3x2 Position"
  rect 1.5x1.5 hole 0.9: 1(0,0)
  round 1.5 hole 0.9: 2(2.54,0) 3(5.08,0) 4(0,2.54) 5(2.54,2.54) 6(5.08,2.54)
  silkscreen extent -1.27,-1.27 6.35,3.81
"HEADER 4PIN 2MMPITCH" [mil]
  rect 52x52 hole 32: 1(0,1.06)
  round 52 hole 32: 2(0,-77.94) 3(0,-156.94) 4(0,-235.94)
  silkscreen extent -50,-285 50,50
"HEADER 6x2 .1\" Pitch" [mil]
  rect 58x58 hole 38: 1(0,0)
  round 58 hole 38: 2(0,-100) 3(0,-200) 4(0,-300) 5(0,-400) 6(0,-500) 7(100,0) 8(100,-100) 9(100,-200) 10(100,-300) 11(100,-400) 12(100,-500)
  silkscreen extent -45,-545 150,50
KMR231GLFS [mm]
  rect 1x1 smd: 1(0,-1.6) 2(0,0) 3(5,-1.6) 4(5,0)
  silkscreen extent -0.84,-2.4 5.94,0.8
MIC2026 [mm]
  rect 1.2x0.6 smd: 1(-0.2,0)
  oval 1.2x0.6 smd: 2(-0.2,-1.27) 3(-0.2,-2.54) 4(-0.2,-3.81) 5(5,-3.81) 6(5,-2.54) 7(5,-1.27) 8(5,0)
  silkscreen extent -1.14,-4.44 5.97,0.76
NR5030 [mm]
  rect 1.5x4 smd: 1(-1.8,0) 2(1.8,0)
  silkscreen extent -2.92,-2.41 2.92,2.41
"OSC 008-0288-0_F" [mm]
  rect 0.9x1 smd: 1(0,-1.55) 2(2.15,-1.55) 3(2.15,0) 4(0,0)
  silkscreen extent -0.82,-2.38 2.94,0.84
"SKYWIRE SOCKET" [mm]
  rect 1.321x1.321 hole 0.8: 1(0,0)
  round 1.321 hole 0.8: 2(0,-2) 3(0,-4) 4(0,-6) 5(0,-8) 6(0,-10) 7(0,-12) 8(0,-14) 9(0,-16) 10(0,-18) 11(22,-18) 12(22,-16) 13(22,-14) 14(22,-12) 15(22,-10) 16(22,-8) 17(22,-6) 18(22,-4) 19(22,-2) 20(22,0)
  silkscreen extent -3.94,-26.05 25.65,8.38
SN74CBT3253CDBQR [mm]
  rect 1.6x0.4 smd: 1(0,0)
  oval 1.6x0.4 smd: 2(0,-0.635) 3(0,-1.27) 4(0,-1.905) 5(0,-2.54) 6(0,-3.175) 7(0,-3.81) 8(0,-4.445) 9(5.4,-4.445) 10(5.4,-3.81) 11(5.4,-3.175) 12(5.4,-2.54) 13(5.4,-1.905) 14(5.4,-1.27) 15(5.4,-0.635) 16(5.4,0)
  silkscreen extent -1.11,-4.93 6.57,0.53
SN74LVC2G125DCUR [mm]
  rect 0.75x0.25 smd: 1(0,0)
  oval 0.75x0.25 smd: 2(0,-0.5) 3(0,-1) 4(0,-1.5) 5(3.1,-1.5) 6(3.1,-1) 7(3.1,-0.5) 8(3.1,0)
  silkscreen extent -0.69,-1.87 3.73,0.37
SOIC8 [mm]
  rect 1.5x0.55 smd: 1(0,0)
  oval 1.5x0.55 smd: 2(0,-1.27) 3(0,-2.54) 4(0,-3.81) 5(5.4,-3.81) 6(5.4,-2.54) 7(5.4,-1.27) 8(5.4,0)
  silkscreen extent -1.02,-4.45 6.48,0.64
SOT-23-3 [mm]
  rect 0.7x1 smd: 1(0,0) 2(0.95,2.4) 3(1.9,0)
  silkscreen extent -0.64,-0.82 2.54,3.23
SRF2012-900YA [mm] "SRF2012-900YA Chip Array, Flat, 4-Leads, Pitch 0.74mm,  Body 1.20x2.00mm,  IPC Medium Density"
  rect 0.75x0.45 smd: 1(-1,0.37) 2(-1,-0.37) 3(1,-0.37) 4(1,0.37)
  silkscreen extent -1.83,-1.02 1.65,1.02
TP [mil]
  round 60 hole 30: 1(0,0)
  silkscreen extent -40,-35 40,35
TPS54229DDA [mm]
  rect 2.15x0.45 smd: 1(0,0)
  oval 2.15x0.45 smd: 2(0,-1.27) 3(0,-2.54) 4(0,-3.81) 5(5.75,-3.81) 6(5.75,-2.54) 7(5.75,-1.27) 8(5.75,0)
  rect 2.6x3.3 smd: 9(2.906,-1.919)
  silkscreen extent -1.52,-4.44 7.25,0.64
"TSSOP8 4.4x3 CASE 948AL-01" [mm]
  rect 1.2x0.4 smd: 1(0,0)
  oval 1.2x0.4 smd: 2(0,-0.65) 3(0,-1.3) 4(0,-1.95) 5(6,-1.95) 6(6,-1.3) 7(6,-0.65) 8(6,0)
  silkscreen extent -0.93,-2.46 6.84,0.53
"UFL TO SMA" [mm]
  rect 2.5x2.5 hole 1.651: 1(0,5.08) 1(0,0) 1(5.08,0) 1(5.08,5.08)
  silkscreen extent -1.7,-1.71 6.81,6.73
USB2514 [mm]
  oval 0.9x0.28 smd paste+0 mask+0: 1(-2.75,2)
  rect 0.9x0.28 smd paste+0 mask+0: 2(-2.75,1.5) 3(-2.75,1) 4(-2.75,0.5) 5(-2.75,0) 6(-2.75,-0.5) 7(-2.75,-1) 8(-2.75,-1.5) 9(-2.75,-2) 19(2.75,-2) 20(2.75,-1.5) 21(2.75,-1) 22(2.75,-0.5) 23(2.75,0) 24(2.75,0.5) 25(2.75,1) 26(2.75,1.5) 27(2.75,2)
  rect 0.28x0.9 smd paste+0 mask+0: 10(-2,-2.75) 11(-1.5,-2.75) 12(-1,-2.75) 13(-0.5,-2.75) 14(0,-2.75) 15(0.5,-2.75) 16(1,-2.75) 17(1.5,-2.75) 18(2,-2.75) 28(2,2.75) 29(1.5,2.75) 30(1,2.75) 31(0.5,2.75) 32(0,2.75) 33(-0.5,2.75) 34(-1,2.75) 35(-1.5,2.75) 36(-2,2.75)
  rect 3.7x3.7 smd paste+0 mask+0: 37(0,0)
  silkscreen extent -3.56,-3.56 3.56,3.56
"USB MINI B" [mm] "UX60-MB-5S8"
  rect 0.5x1.4 smd: 1(-1.6,0) 2(-0.8,0) 3(0,0) 4(0.8,0) 5(1.6,0)
  rect 1.524x4.5 hole 0.813 slot 3.607 at 90 deg: 6(-3.65,-2.5)
  rect 1.524x4.5 hole 0.813 slot 3.6 at 90 deg: 6(3.65,-2.5)
  silkscreen extent -5.23,-5.3 5.16,1.15
"USBA FCI VERT" [mil]
  round 55 hole 35 mask+0: 1(107.09,28.74) 2(107.09,107.48) 3(107.09,186.22) 4(107.09,264.96)
  round 85 hole 65: 5(0,275.59) 5(0,0) 5(214.17,275.59) 5(214.17,0)
  silkscreen extent -55,-55 270,330
"XBEEPRO RPSMA" [mil]
  rect 52x52 hole 32: 1(0,0)
  round 52 hole 32: 2(0,-79) 3(0,-158) 4(0,-237) 5(0,-316) 6(0,-395) 7(0,-474) 8(0,-553) 9(0,-632) 10(0,-711) 11(866,-711) 12(866,-632) 13(866,-553) 14(866,-474) 15(866,-395) 16(866,-316) 17(866,-237) 18(866,-158) 19(866,-79) 20(866,0)
  silkscreen extent -50,-1044 915,150

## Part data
ANT1 ANT2 ANT3: library part "MTG UFL to SMA", "Antenna Socket"
C1 C2 C8 C9 C10 C19 C39: library part "Cap 10uF 10V 10% X5R 0603 CER", "Cap 10uF 10V 10% X5R 0603 CER"
C3 C5 C6 C12 C13 C18 C20 C21 C22 C23 C24 C25 C26 C29 C32 C34 C38 C47 C51 C53 C54: library part "Cap 0.1uF 16V 10% X7R 0603 CER", "Cap 0.1uF 16V 10% X7R 0603 CER"
C4: library part "Cap 0.47uF 16V 10% X7R 0603 CER", "Cap 0.47uF 16V 10% X7R 0603 CER"
C7: library part "Cap 22pF 50V 10% X7R 0603 CER", "Cap 22pF 50V 10% X7R 0603 CER"
C11 C17 C27 C40 C42 C45 C50: library part "Cap 1uF 10V 10% X7R 0603 CER", "Cap 1uF 10V 10% X7R 0603 CER"
C14 C16: library part "Cap 18pF 100V 5% NP0 0603 CER", "Cap 18pF 100V 5% NP0 0603 CER"
C15 C36 C37: library part Cap, "Cap"
C28 C33 C44 C48: library part "Cap 100uF 6.3V 20% X5R 1206 CER", "Cap 100uF 6.3V 20% X5R 1206 CER"
C30 C35 C52: library part "Cap 4.7UF 10V Y5V 0603", "Cap 4.7UF 10V Y5V 0603"
C41 C43 C46 C49: library part "Cap 1nF 50V 10% X7R 0603 CER", "Cap 1nF 50V 10% X7R 0603 CER"
D2 D3 D4 D14 D16: "LED GREEN  SMD"
D5 D7 D9 D11 D12: library part "D TVS USB HIGH SPEED D5V0F4U6SO-7", "USB ESD Protection D5V0F4U6SO-7"
D6 D8 D10 D13: library part D_LED_GREEN, "LED GREEN  SMD"
Fiducial1 Fiducial2 Fiducial3 Fiducial4 Fiducial5 Fiducial6: library part Fiducial
J1: library part "Header 2", "Header, 2-Pin"
J2 J4: library part "J USB A REC"
J3: library part "J USB MINI B"
J5: library part "Header 4PIN 2mmpitch"
J7: "Header, 3-Pin, Dual row"
J14: "ZIGBEE-PRO W/RPSMA ANT"
L1: library part "L 6.8UH 2.3A 30% SMD NRS5030T6R8MMGJ", "INDUCTOR 6.8UH 2.3A 30% SMD5030"
L2 L3 L4 L5: library part "L USB Common Choke 90OHM SRF2012-900YA"
OSC1: library part "CRYSTAL 24MHz 18pF", "CRYSTAL 24MHz 18pF"
P8: library part "J BBBC SOCKET P8"
P9: library part "J BBBC SOCKET P9"
Q1 Q2: library part "Q MOSFET N-CH 25V 220MA SOT-23", "MOSFET N-CH 25V 220MA SOT-23"
R1 R9 R48: library part "RES 1K 1/10W 1% 0603", "RES 1K 1/10W 1% 0603"
R2 R21: library part "RES 124 1/10W 1% 0603", "RES 124 1/10W 1% 0603"
R3 R22 R24 R25 R26 R27 R30 R34 R39 R41 R42 R43 R44 R50 R51 R52 R53 R54 R55 R56: library part "RES 10K 1/10W 1% 0603", "RES 10K 1/10W 1% 0603"
R4 R23: library part "RES 0.1 1/3W 1% 0805", "RES 0.1 1/3W 1% 0805"
R5: library part "RES 93.1K 1% 1/10W 0603"
R6: library part "RES 22.1K 1/10W 1% 0603 SMD"
R7 R8 R10 R13 R14 R33: library part "RES 100K 1/10W 1% 0603", "RES 100K 1/10W 1% 0603"
R11 R12: library part "RES 5.6k 1/10W 1% 0603", "RES 5.6k 1/10W 1% 0603"
R15: library part "RES 12K 1/10W 1% 0603", "RES 12K 1/10W 1% 0603"
R16 R17 R18 R20 R38: library part "RES 330 1/10W 1% 0603", "RES 330 1/10W 1% 0603"
R19 R28 R31 R32 R45 R46 R47 R63: library part "RES NP"
R29: library part R
R35 R36 R37: library part "RES 4.75k 1/10W 1% 0603", "RES 4.75k 1/10W 1% 0603"
R40: library part "RES 1M 1/10W 1% 0603", "RES 1M 1/10W 1% 0603"
R49: library part "RES 0 1/10W 1% 0603", "RES 0 1/10W 1% 0603"
R57 R58: library part "RES 120 1/10W 1% 0603", "RES 120 1/10W 1% 0603"
R59 R60 R61 R62: library part "RES 33 1/10W 1% 0603", "RES 33 1/10W 1% 0603"
U1: "TPS54229DDA 4.5V-18V 2A"
U8 U9: library part "U SN65HVD234D", "SN65HVD234D CAN Transciever"

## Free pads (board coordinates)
  round 200 on Keep-Out: 0(2855,2155) 1(2855,4055) 2(5455,2280)
  round 120 hole 120: 1(2855,2155) 1(2855,4055) 1(5455,2280) 1(5455,3930)
  round 180 on Keep-Out: 2(5455,3930)

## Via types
v1: diameter 35, hole 15, Top Layer to Bottom Layer, 320 vias

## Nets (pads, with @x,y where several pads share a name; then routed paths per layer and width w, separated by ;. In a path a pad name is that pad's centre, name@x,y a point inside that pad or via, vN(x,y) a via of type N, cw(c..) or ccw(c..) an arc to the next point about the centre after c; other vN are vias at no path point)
BB_UART1_RX: P9.26 U7.4 U11.5 | length 1496.7
  Top Layer w12: v1@3765.5,2731.55 3765.5,2489.5 3809.5,2445.5 3832.63,2445.5 3877.66,2400.47 U7.4@3912.48,2400.47 3940.62,2400.47 3966.28,2374.82 3966.28,2270.43 3998,2238.71 3998,2201.19 4037.19,2162 4172.81,2162 4215.81,2205 P9.26@4255,2205 ; 3767.81,2933.45 v1(3767.81,3085.7) ; v1@3767.84,2906.18 3767.84,2933.43
  Signal Layer 1 w12: v1(3772.43,2746.55) 3775.93,2750.05 v1(3775.93,2907.39)
  Bottom Layer w12: v1(3767.81,3085.7) 3813.52,3085.7 3895.13,3167.31 U11.5@3895.13,3192.95
BB_UART1_TX: P9.24 U7.12 U11.6 | length 1595.1
  Top Layer w12: U7.12@3699.88,2425.47 3752.59,2425.47 v1(3758.66,2419.4) ; v1(3870,3240) 3861.29,3231.29 3861.29,2844.96 3922.76,2783.49 3922.76,2595.36 v1(3909.73,2582.33)
  Bottom Layer w12: v1(3758.66,2419.4) v1@3763.51,2419.4 ; v1(3870,3240) 3874.37,3235.63 U11.6@3874.37,3192.95 ; v1(3909.73,2582.33) 3898.93,2582.33 3860.21,2543.61 3860.21,2500.86 3778.76,2419.4 v1@3763.51,2419.4 ; P9.24@4155,2205 4155,2322.66 4093.16,2384.5 3798.42,2384.5 v1@3763.51,2419.4
BB_UART2_RX: J14.2 P9.22 U7.5 | length 2103.8
  Top Layer w12: v1(2755,2665) 2760,2660 3120.24,2660 3131.74,2671.5 3399.39,2671.5 3620,2892.11 3707.07,2892.11 3802.93,2796.25 3802.93,2733.92 3792.33,2723.32 3792.33,2489.54 3805.26,2476.61 3828.39,2476.61 3879.53,2425.47 U7.5@3912.48,2425.47 3955.02,2425.47 3999.27,2381.22 3999.27,2264.31 4055,2208.58 P9.22@4055,2205
  Bottom Layer w12: J14.2@2709,2801.69 2709,2711 v1(2755,2665)
BB_UART2_TX: J14.3 P9.21 U7.11 | length 2354.1
  Top Layer w12: v1(2725,2635) 2725.5,2634.5 3121.61,2634.5 3139.61,2652.5 3462.5,2652.5 3651.61,2841.61 3722.98,2841.61 3751.09,2813.5 3751.09,2773.73 3735.99,2758.63 3735.99,2578.06 3746.5,2567.55 3746.5,2474.69 3770.72,2450.47 ; U7.11@3699.88,2450.47 3770.72,2450.47 ; P9.21@4055,2105 3998,2162 3837.19,2162 3805.62,2193.57 3805.62,2370.48 3789.16,2386.94 3789.16,2432.04 3770.72,2450.47
  Bottom Layer w12: v1(2725,2635) 2725.5,2634.5 2767.63,2634.5 2785.5,2652.37 2785.5,2799.19 J14.3@2788,2801.69
BB_UART4_RX: P9.11 U7.6 | length 687.1
  Top Layer w10: v1(3829.71,2513.49) 3826.22,2510 3841.22,2495 3880.63,2455.6 3907.36,2455.6 U7.6@3912.48,2450.47
  Bottom Layer w10: P9.11@3555,2105 3604.04,2154.04 3668.9,2154.04 3710.88,2196.01 3710.88,2413.34 3811.02,2513.49 v1(3829.71,2513.49)
BB_UART4_TX: P9.13 U7.10 | length 470.2
  Top Layer w12: P9.13@3655,2105 3604.81,2155.19 3604.81,2447.95 3632.34,2475.47 U7.10@3699.88,2475.47
BB_UART5_RX: P8.38 U7.3 | length 2751.6
  Top Layer w12: v1(3820,2415) 3821.01,2415 3860.54,2375.47 U7.3@3912.48,2375.47 ; v1(3893.03,2533.3) 3891.7,2533.3 3821.93,2603.07 3821.93,2904.52 3802.23,2924.22 3802.23,3618.83 3893.69,3710.28 3893.69,3882.88 3998,3987.19 3998,4027.45 4022.87,4052.32 4802.32,4052.32 P8.38@4855,4105
  Bottom Layer w12: v1@3820,2423.53 3886.17,2489.7 3886.17,2526.43 v1(3893.03,2533.3)
BB_UART5_TX: P8.37 U7.13 | length 2686.9
  Top Layer w12: v1@3637.88,2422.75 3660.16,2400.47 U7.13@3699.88,2400.47 ; 3842.29,2941.64 3842.1,2941.83 ; v1(3858.46,2639.34) 3858.46,2796.54 3842.1,2812.9 3842.1,2941.83 ; P8.37@4855,4005 4791.1,3941.1 3998.22,3941.1 3933.29,3876.17 3933.29,3659.3 3835,3561.01 3835,2948.93 3842.1,2941.83
  Bottom Layer w12: v1(3640,2440) 3647.13,2447.13 3647.13,2460.35 3675.38,2488.59 3675.38,2548.23 3693.24,2566.1 3801.26,2566.1 3858.46,2623.3 v1(3858.46,2639.34)
CAN0_D: R61.1 U10.11 | length 1735.2
  Top Layer w12: U10.11@4147.42,2377.54 4147.42,2431.26 4164.12,2447.96 v1(4164.12,2478.66)
  Bottom Layer w12: R61.1@3241.52,3355.34 3268.92,3327.94 3358.95,3327.94 3370,3316.89 3456.16,3316.89 3490.69,3282.36 3490.69,3162.68 3639.96,3013.42 3643.15,3013.42 3643.62,3012.94 4051.34,3012.94 4081.2,3012.94 4092.5,3012.94 4112.92,2992.52 4112.92,2992.44 4119.65,2985.71 4120.1,2985.71 4145.29,2960.52 4145.29,2960.07 4147.5,2957.86 4147.5,2866.63 4157.57,2856.56 4157.57,2856.26 4158.48,2855.35 4158.48,2484.29 v1(4164.12,2478.66)
CAN0_R: R62.1 U10.5 | length 1349.1
  Top Layer w12: U10.5@4172.42,2590.14 4172.42,2640.22 ; 4172.42,2644.27 v1(4197.12,2668.97)
  Bottom Layer w12: R62.1@3505,3356.38 3516.41,3344.97 3516.41,3177.23 3661.69,3031.94 4059.21,3031.94 4073.33,3031.94 4073.58,3032.2 4100.11,3032.2 4127.6,3004.71 4127.97,3004.71 4164.29,2968.39 4164.29,2968.02 4166.5,2965.81 4166.5,2874.5 4176.57,2864.43 4176.57,2864.13 4221.98,2818.72 4221.98,2771.03 4236.48,2756.53 4236.48,2708.33 v1(4197.12,2668.97)
CAN0H: J7.5 R58.2 U8.7 | length 1206.7
  Top Layer w12: J7.5@2500,2695 2542.53,2737.53 2617.62,2737.53 2620.14,2735 3180,2735 3223,2778 3223,2958 v1(3230,2965)
  Bottom Layer w12: v1@3230,2975 3340.45,3085.45 R58.2@3340.45,3117.82 ; R58.2@3347.19,3117.82 U8.7@3347.19,3186.55
CAN0L: J7.4 R58.1 U8.6 | length 1459.6
  Top Layer w12: 2430,2705 2487.69,2762.69 3120.15,2762.69 3143,2785.54 3143,2864.5 3143.5,2865 3143.5,2927.8 3225,3009.3 v1(3225,3015)
  Bottom Layer w15: v1(3225,3015) 3258,3048 3258,3207.23 3284.62,3233.85 3352.48,3233.85 ; 3354.41,3233.85 3352.48,3233.85 ; R58.1@3399.07,3117.82 3397.19,3119.7 U8.6@3397.19,3186.55 3397.19,3191.07 3357.68,3230.58 3355.75,3230.58 3352.48,3233.85
CAN1_D: R59.1 U11.3 | length 140.1
  Bottom Layer w10: R59.1@3775,3238.62 3776.53,3238.62 3825.15,3287.24 3862.11,3287.24 3874.37,3299.5 U11.3@3874.37,3315
CAN1_R: R60.1 U11.2 | length 102.3
  Bottom Layer w12: R60.1@3775,3343.62 3844.45,3343.62 3854.68,3333.38 U11.2@3854.68,3315
CAN1H: J7.2 R57.2 U9.7 | length 2421.2
  Top Layer w12: J7.2@2500,2595 2539.86,2595 2582.38,2552.47 2617.62,2552.47 2694.5,2629.36 2694.5,2647.63 2742.37,2695.5 2783.5,2695.5 2794,2685 3118.37,2685 3123.87,2690.5 3325.5,2690.5 3410,2775 3410,2920 3245,3085 3245,3455.75 3310,3520.75 v1(3310,3540)
  Bottom Layer w12: v1(3310,3540) 3350,3580 3608.66,3580 3667.21,3521.45 R57.2@3667.21,3470.93 ; U9.7@3663.66,3397.72 R57.2@3663.66,3470.93
CAN1L: J7.1 R57.1 U9.6 | length 2263.9
  Top Layer w12: J7.1@2400,2595 2439.86,2595 2482.38,2637.53 2654.04,2637.53 2731.01,2714.5 3244.5,2714.5 3301,2771 3301,2874 3275,2900 3275,3008.13 3220,3063.13 v1(3220,3480)
  Bottom Layer w12: v1(3220,3480) 3225,3475 3300,3475 3374.16,3549.16 3565.24,3549.16 3608.59,3505.81 R57.1@3608.59,3470.93
  Bottom Layer w15: U9.6@3613.66,3397.72 R57.1@3613.66,3470.93
CANMUX_OE#: R43.2 U10.1 U10.15 | length 290.2
  Top Layer w10: U10.15@4247.42,2377.54 v1@4247.42,2428.99 ; v1(4250,2505) 4250,2510 4272.42,2532.42 ; U10.1@4272.42,2590.14 4272.42,2532.42 ; R43.2@4330,2545 4272.42,2545 4272.42,2532.42
  Bottom Layer w10: v1(4250,2505) 4250,2445 v1(4260,2435)
CFG_SEL0: R14.1 U2.24 | length 284
  Bottom Layer w10: R14.1@4147.85,3139.41 4198.76,3088.5 4214.78,3088.5 4217.78,3085.5 4242.22,3085.5 4281.22,3124.5 4311.96,3124.5 4314.26,3122.2 U2.24@4392.45,3122.2
GND: ANT1.1 ANT2.1 ANT3.1 C1.2 C2.2 C3.2 C4.1 C6.2 C8.2 C9.2 C10.2 C11.2 C12.2 C13.2 C14.1 C15.2 C16.1 C17.2 C18.2 C19.2 C20.2 C21.2 C22.2 C23.2 C24.2 C25.2 C26.2 C27.2 C28.2 C29.2 C30.2 C32.2 C33.2 C34.2 C35.2 C36.2 C37.2 C38.2 C39.2 C40.2 C41.2 C42.2 C43.2 C44.2 C45.2 C46.2 C47.2 C48.2 C49.2 C50.2 C51.2 C52.2 C53.2 C54.2 D1.A D2.2 D3.2 D5.2 D6.2 D7.2 D8.2 D9.2 D10.2 D11.2 D12.2 D13.2 D16.2 FB2.1 FB4.1 FB6.1 FB8.1 FB9.1 FB11.1 FB12.1 J6.4 J6.10 J6.11 J6.15 J7.3 J7.6 J8.1 J8.2 J14.10 OSC1.2 OSC1.4 P8.1 P8.2 P9.1 P9.2 P9.43 P9.44 P9.45 P9.46 Q1.3 Q2.3 R6.1 R8.1 R13.2 R14.2 R15.1 R19.1 R22.2 R24.1 R26.1 R27.1 R30.2 R31.1 R32.1 R33.2 R39.1 R42.2 R43.1 R44.2 R45.1 R47.1 R54.1 R56.2 R63.1 SW1.2 SW1.4 U1.4 U1.9 U2.11 U2.37 U3.6 U4.6 U5.4 U7.8 U8.2 U9.2 U10.8 U11.4 | length 8304.2
  Top Layer w12: R30.2@3291.57,3250.32 3291.57,3258.89 v1(3330.12,3297.44) ; v1@3334.73,3290.73 3340,3285.46 C17.2@3340,3130 ; v1(3346.88,3466.71) 3356.39,3476.22 3441.53,3476.22 R47.1@3464.59,3453.15 ; C21.2@3913.6,3085.7 C21.2@3913.6,3085.93 ; U5.4@3956.25,3141.34 U5.4@3962.48,3141.34 ; R44.2@4040.23,2497.44 R44.2@4040.23,2498.93 ; 4089.1,2556.9 4095.02,2562.82 U10.8@4095.02,2590.14 ; v1@4231.28,3116.79 4237.06,3122.57 C22.2@4237.06,3179.39 ; v1(4520,3165) v1@4526.23,3171.23 ; C13.2@4533.76,2989.2 4533.76,3031.24
  Top Layer w15: D1.A@2892.83,2377.49 D1.A@2897.52,2382.18 ; v1(3657.15,3338.8) 3711.93,3393.58 R39.1@3743.53,3393.58
  Top Layer w20: v1@3464.29,3615.71 R45.1@3496.37,3615.71 ; v1@3480.28,3873.33 D16.2@3532.15,3873.33 ; v1(3530,2340) 3573.47,2340 R27.1@3573.47,2378.03 ; C39.2@3634.45,3026.82 3634.45,3090.2 3662.38,3118.13 v1(3662.38,3131.94) 3662.38,3133.94 3640.73,3155.58 R42.2@3640.73,3181.51 ; Q2.3@3860,3854.8 3860,3901.18 v1(3860.23,3901.41) ; C21.2@3911.8,3085.93 3911.8,3116.8 3936.34,3141.34 U5.4@3956.25,3141.34 ; U7.8@3912.48,2500.47 v1@3934.21,2522.2 ; v1(3919.52,3487.37) 3919.52,3509.52 3928.62,3518.62 R24.1@3970,3518.62 ; R63.1@3979.33,3773.95 4097.11,3773.95 v1(4097.3,3773.76) ; J6.4@4271.89,2740.37 4265.87,2740.37 4265.87,2662.16 4317.4,2610.64 R43.1@4318.87,2610.64 ; C23.2@4284.46,2841.78 4285.38,2842.7 C25.2@4370.64,2842.7 ; v1(4362.23,2479.01) 4377.91,2479.01 4409.86,2510.97 4409.86,2546.29 4419.72,2556.15 4419.72,2598.91 R54.1@4385,2633.62 ; v1(4542.93,2456.81) 4595.03,2508.9 D6.2@4596.95,2508.9
  Top Layer w25: R43.1@4318.87,2610.64 R43.1@4324.26,2610.64
  Top Layer w30: ANT2.1@2600,2475 2630,2505 D2.2@2730,2505 D3.2@2730,2580 ; D1.A@2892.83,2377.49 D1.A@2922.66,2347.65 2984.86,2347.65 2997.21,2360 v1(3005,2360) ; R26.1@4040.23,2451.49 R44.2@4040.23,2497.44 ; R44.2@4041.73,2498.93 4058.77,2498.93 v1(4089.1,2529.26) 4089.1,2556.9 4089.1,2559.38 U10.8@4092.55,2562.82 ; v1(4135,3435) C53.2@4185,3435 C53.2@4195,3435 ; C27.2@4172.8,2918.88 4172.8,2938 4228.02,2993.22 4228.02,3121.01 v1@4230.21,3123.2 ; v1(4230,3115) C22.2@4230,3172.33 ; R8.1@4262.82,3837.26 v1@4365.73,3837.26 ; R43.1@4324.26,2610.64 4347.25,2633.62 R54.1@4385,2633.62 ; v1(4376.75,3772.6) C11.2@4428.04,3772.6 ; C42.2@4619.13,3833.95 4652.3,3833.95 v1@4652.3,3859.91 ; 4658.6,3833.95 4767.12,3833.95 4806.1,3872.93 D13.2@4997.94,3872.93 ; J6.11@4744.33,3606.51 4758.39,3620.57 C52.2@4865.25,3620.57 ; D12.2@4774.71,2902.46 v1@4812.56,2902.46 ; v1@4835.78,3265.4 C54.2@4835.78,3295.89 ; v1(4879.95,2592.93) U3.6@4879.95,2640.14 ; J8.1@4894.78,2417.09 4925.92,2385.95 FB4.1@4964.21,2385.95 ; v1(4946.46,3374.05) 4976.73,3404.31 U4.6@5026.98,3404.31 ; v1(4972.41,2552.85) 5018.03,2507.24 C44.2@5023.98,2507.24 ; C51.2@5020,3035 C49.2@4955,3035 5053.41,3133.41 ; C35.2@5047.43,2640.73 R32.1@5169.56,2640.73 ; v1(5103.42,3957.67) 5125.26,3935.83 C15.2@5125.26,3916.18 5215.65,3916.18 ; C48.2@5135,2906.1 5101.38,2872.48 FB8.1@5101.38,2840 5101.38,2837.98 5136.94,2802.42 v1(5136.94,2760.76) ; C28.2@5135.93,3254.61 5141.77,3260.45 v1@5141.77,3315.49 ; v1(5155,3100) 5148.3,3106.7 C40.2@5148.3,3133.41 5053.41,3133.41 ; R32.1@5169.56,2643.86 R32.1@5169.56,2640.73 ; v1(5187.18,2607.95) 5169.56,2625.56 R32.1@5169.56,2640.73 ; v1(5210.81,3958.95) 5215.65,3954.11 5215.65,3916.18 ; SW1.4@5227.98,3778.11 SW1.2@5227.98,3581.26 5227.98,3574.77 v1(5201.93,3548.73) 5201.93,3499.9 FB11.1@5210.38,3491.45 5269.99,3491.45 FB6.1@5270.42,3491.02 ; 5288.93,2543.93 5288.93,2417.96 5311.7,2440.73 ANT1.1@5385.83,2440.73 ; 5289.03,2534.7 5289.03,2543.93 ANT1.1@5385.83,2640.73 R32.1@5169.56,2640.73 ; v1(5313.12,3956.15) 5275.12,3918.14 FB9.1@5244.5,3918.14 5242.54,3916.18 5215.65,3916.18 ; 5053.41,3133.41 4972.63,3133.41 C50.2@4970.27,3135.77 5054.23,3135.77 5055,3135 5053.41,3133.41
  Top Layer w100: D1.A@2922.66,2347.65 2922.66,2309.37 3055,2177.03 P9.1@3055,2105
  Bottom Layer w12: U8.2@3347.19,3399.15 3347.19,3449.22 ; v1(3662.38,3131.94) 3663.66,3133.22 U9.2@3663.66,3185.12 ; U11.4@3894.05,3315 3914.13,3294.92 3914.13,3172.51 v1@3939.7,3146.94 ; U2.11@4559.77,2994.25 4559.77,3044.77 v1(4560,3045)
  Bottom Layer w20: v1(3530,2340) 3530.66,2339.34 3586.47,2339.34 C6.2@3621.19,2374.06 ; C33.2@3645.39,2833.81 3645.39,2845.98 v1(3725.9,2926.48) ; v1@3939.7,3146.94 R33.2@3982.28,3189.51 ; v1(4080,3170) 4089.96,3160.04 R14.2@4089.96,3139.21 ; R13.2@4089.48,3083.79 R14.2@4089.48,3139.21
  Bottom Layer w30: v1(3005,2360) 3002.79,2360 3000,2362.79 3005.62,2368.41 C1.2@3106.35,2368.41 C3.2@3165.72,2368.41 ; v1(4400.72,3365.73) 4417.47,3348.98 OSC1.2@4495.35,3348.98 ; OSC1.4@4578.08,3403.33 OSC1.4@4580,3403.33 ; OSC1.4@4580,3410 4632.76,3410 C14.1@4643.09,3399.67 ; C14.1@4640.86,3397.44 4642.46,3395.85 C12.2@4700.95,3395.85 ; C12.2@4703.45,3393.76 4705.48,3395.79 R15.1@4761.15,3395.79 ; v1(4870.63,3010.28) 4892.41,2988.5 4892.41,2984.43 D7.2@4941.05,2984.43 ; v1(4946.46,3374.05) 4946.46,3374.88 C36.2@4968.92,3397.33 R31.1@4968.92,3453.55 ; v1(4972.41,2552.85) 4976.31,2552.85 v1@4979.4,2555.94 ; v1@4977.45,2557.89 D9.2@5050.78,2557.89 ; D5.2@4987.03,3135.41 4987.03,3101.25 5013.75,3101.25 v1(5020,3095) ; v1(5201.93,3548.73) 5237.4,3548.73 FB2.1@5238.99,3550.32 5260.83,3572.16 D11.2@5260.83,3610.03
  Bottom Layer w40: R6.1@3546.71,2577.98 3584.69,2540 v1(3615,2540) 3594.8,2560.2 C34.2@3594.8,2576.83
  Bottom Layer w50: 3252.84,2537.44 3227.39,2562.9 3180.22,2562.9 3194.32,2576.99 C8.2@3366.23,2576.99
  other v1: 2975,2070 3105,2070 3205,2070 3505,2070 3605,2070 3705,2070 3805,2070 3905,2070 4005,2070 4105,2070 4205,2070 4305,2070 4405,2070 4505,2070 4605,2070 4700,2070 4800,2070 4900,2070 5000,2070 5100,2070 2598.77,2070.56 2751.35,2072.02 5205,2075 5325,2095 2430,2100 5425,2145 3793.41,2154.2 4212.05,2153.5 2361.48,2155.27 3505,2155 4303.54,2156.28 2981.86,2209.51 2326.88,2245.27 2750,2245 3304.36,2250.11 3355.59,2278.28 5580,2305 3162.52,2330 2495.1,2374.75 2328.75,2376.72 3320,2385 3350,2385 3380,2385 3410,2385 3320,2415 3350,2415 3380,2415 3410,2415 3320,2445 3350,2445 3380,2445 3410,2445 3320,2475 3350,2475 3380,2475 3410,2475 2940,2480 3320,2505 3350,2505 3380,2505 3410,2505 3943.84,2529.03 2329.38,2533.72 5485,2545 3180,2555 3648.61,2583.53 3703.92,2644.69 2324.22,2647.36 4629.07,2704.44 4470,2705 4550.28,2705.67 2440.58,2776.2 5626.18,2790.06 4730.06,2793.38 4644.22,2836.5 2325,2840 2440,2840 2570,2840 2750,2840 2905,2840 3060,2840 4324.36,2846.27 3907.77,2884.05 5626.18,2885.06 4808.81,2907.81 3100,2925 3325,2950 4666.79,2979.96 5626.18,2985.06 4765.92,3027.51 4440,3045 4480,3045 4520,3045 3100,3050 4440,3085 4480,3085 4520,3085 4560,3085 5626.18,3095.02 4734.89,3112.54 4440,3125 4480,3125 4520,3125 4558.61,3125.42 3929.32,3144.36 4440,3165 4480,3165 4558.61,3166.49 3100,3175 5626.18,3195.02 4653.89,3243.1 4836.96,3255.67 5626.18,3295.02 3100,3304.35 4109.08,3309.99 5141.13,3316.13 5626.18,3395.02 4629.97,3422.89 3100,3425 3100,3550 5625,3575 3656.98,3584.09 2325,3620 2440,3620 2570,3620 2750,3620 2905,3620 3065,3620 3225,3625 3455,3625 5625,3705 4702.31,3719.65 2323.15,3766.62 5336.32,3785.07 3455.75,3799.64 3684.22,3802.16 4370.83,3839.3 5613.22,3839.5 4801.79,3845.5 2900,3850 3100,3850 3300,3850 4650.77,3871.47 3474.34,3881.81 2326.88,3886.86 2500.9,3892.24 5575.99,3902.85 3494.97,3941.36 4905.08,3948.96 5205.53,4056.32 5423.8,4062.62 2393.54,4078.12 5342.91,4099.07 2500.37,4136.11 5206.33,4138.95 2618.96,4140 2718.96,4140 3013.57,4140 3109.71,4140.25 3211.67,4139.98 3308.57,4140 3408.57,4140 3509.44,4140 3609.44,4140 3709.44,4140 3809.44,4140 3904.44,4140 4004.44,4140 4106.61,4140 4206.61,4140 4306.61,4140 4406.61,4140 4501.61,4140 4601.61,4140 4711.56,4140 4811.56,4140 4911.56,4140 5011.56,4140 5106.56,4140
MUX_OE: R56.1 U7.1 U7.15 | length 314.9
  Top Layer w8: R56.1@3632.51,2334.13 3648.84,2350.47 U7.15@3699.88,2350.47 3699.88,2348.9 3761.1,2348.9 v1(3775,2335) ; v1(3860.2,2315.92) 3860.2,2324.36 3861.31,2325.47 U7.1@3912.48,2325.47
  Bottom Layer w8: v1@3766.13,2323.38 3852.74,2323.38 v1(3860.2,2315.92)
MUX_S0: J8.5 R27.2 U7.14 | length 965.6
  Top Layer w10: R27.2@3632.09,2378.03 3634.65,2375.47 U7.14@3699.88,2375.47 v1@3753.67,2375.47
  Signal Layer 1 w10: v1(3755.56,2377.4) 3777.38,2377.4 3777.38,2374.34 3804.5,2347.22 3804.5,2329.9 3847.98,2286.42 3872.42,2286.42 3923.99,2338 4330.4,2338 4365.81,2373.41 4419.87,2373.41 4463.56,2417.09 J8.5@4494.78,2417.09
MUX_S1: J8.6 R26.2 U7.2 | length 815.2
  Top Layer w8: v1(3837.83,2352.36) 3839.72,2350.47 U7.2@3912.48,2350.47 ; v1(3986.79,2441.9) 3991.2,2441.9 R26.2@4040.23,2392.86
  Signal Layer 1 w8: v1(3837.83,2352.36) 3845.1,2359.64 3986.79,2359.64 ; v1(3986.79,2441.9) 3986.79,2359.64 ; J8.6@4394.78,2417.09 4386.02,2417.09 4328.57,2359.64 3986.79,2359.64
NC5: J6.13 Q2.1 | length 894.6
  Top Layer w12: v1(3852.26,3726.95) 3860,3734.69 Q2.1@3860,3780 ; J6.13@4586.85,3606.51 v1@4586.85,3700.55
  Bottom Layer w12: v1(3852.26,3726.95) 4037.52,3726.95 4062.85,3701.62 v1(4586.05,3701.62)
NetC4_2: C4.2 U1.6 | length 93.9
  Bottom Layer w20: U1.6@3479.22,2472.92 3563.55,2472.92 C4.2@3570.32,2466.15
NetC5_1: C5.1 U1.1 | length 139.9
  Top Layer w15: C5.1@3227.87,2397.73 3231.53,2397.73 3264.83,2364.43 v1(3264.83,2326.56)
  Bottom Layer w15: U1.1@3252.84,2372.92 3264.83,2360.93 v1(3264.83,2326.56)
NetC5_2: C5.2 L1.1 U1.3 | length 162.3
  Top Layer w45: 3202.62,2481.61 C5.2@3219.61,2464.61
  Bottom Layer w45: L1.1@3100.98,2482.94 3239.2,2482.94
  other v1: 3188.17,2493.37
NetC6_1: C6.1 U1.8 | length 68.8
  Bottom Layer w20: U1.8@3479.22,2372.92 3480.8,2374.5 3545.11,2374.5 3546.69,2372.92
